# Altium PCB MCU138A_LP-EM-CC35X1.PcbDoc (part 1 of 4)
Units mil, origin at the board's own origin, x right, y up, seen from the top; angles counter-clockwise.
Board outline 2309.44 x 2672.36 mil, 4 copper layers (Top Layer, L02_GND, L03_PWR, Bottom Layer), stack 60 mil thick; 235 components, 167 nets, 678 pads, 887 vias.
Unrouted connection lines stored in the file: 19.
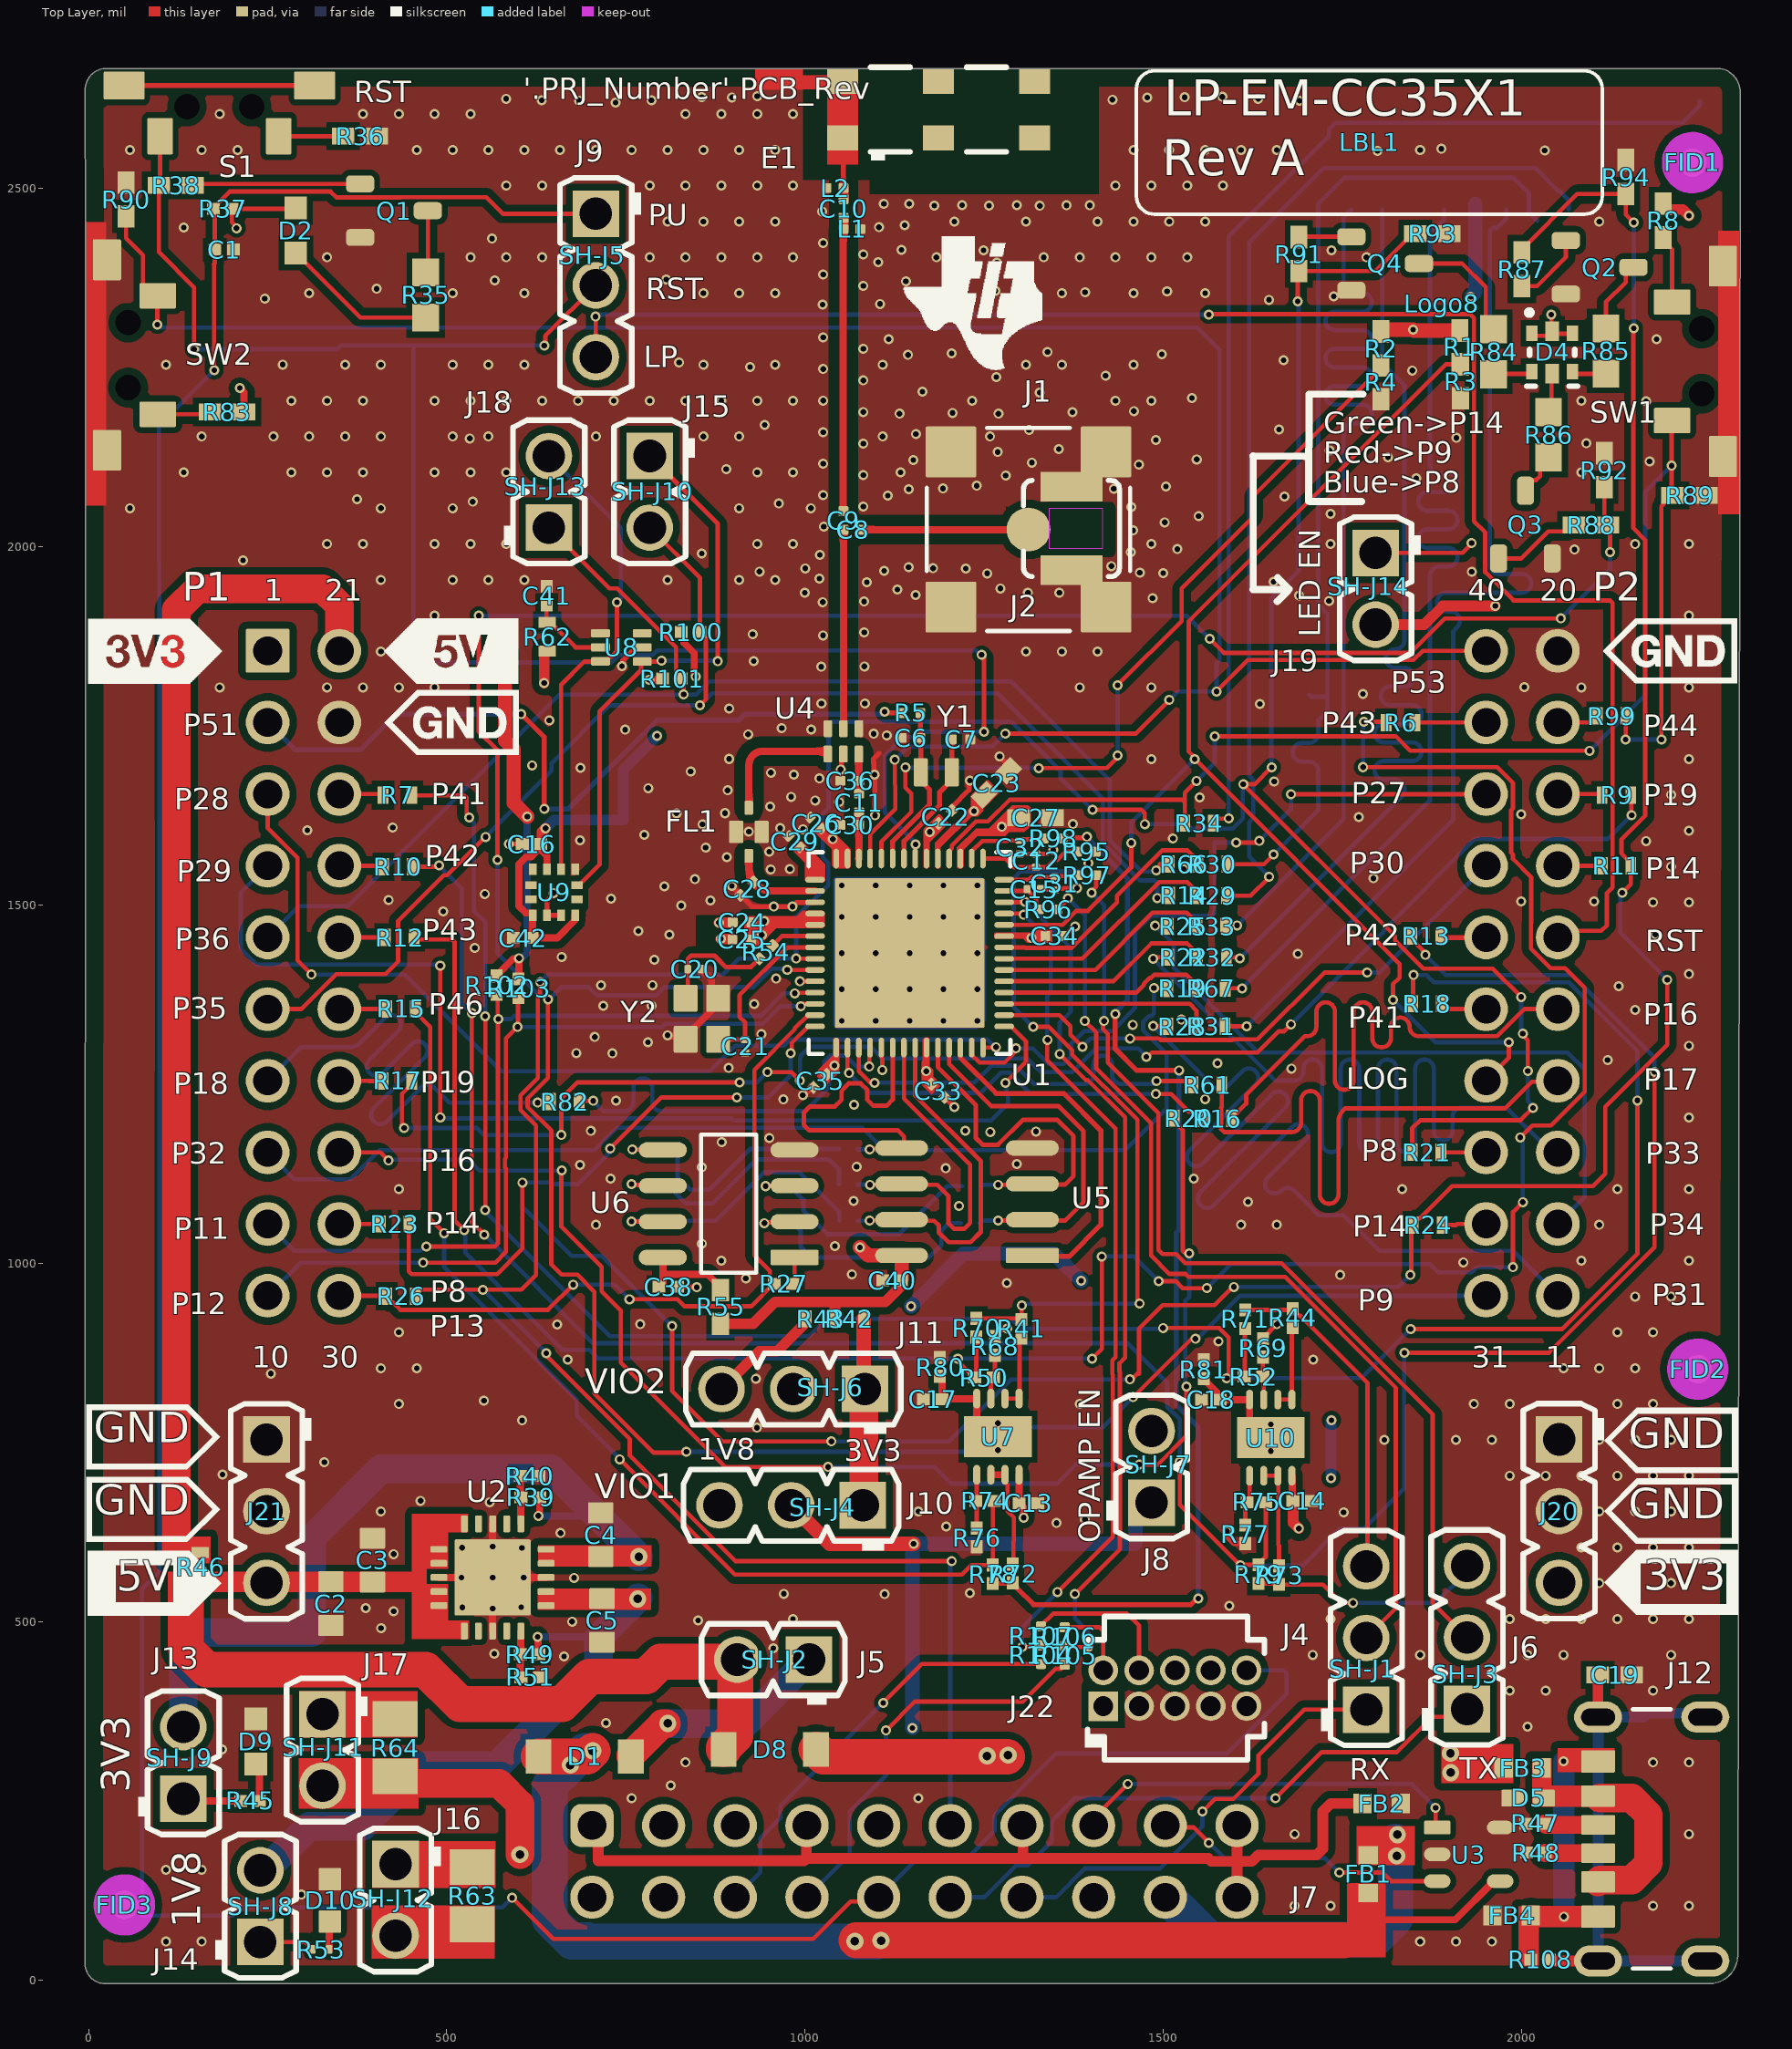
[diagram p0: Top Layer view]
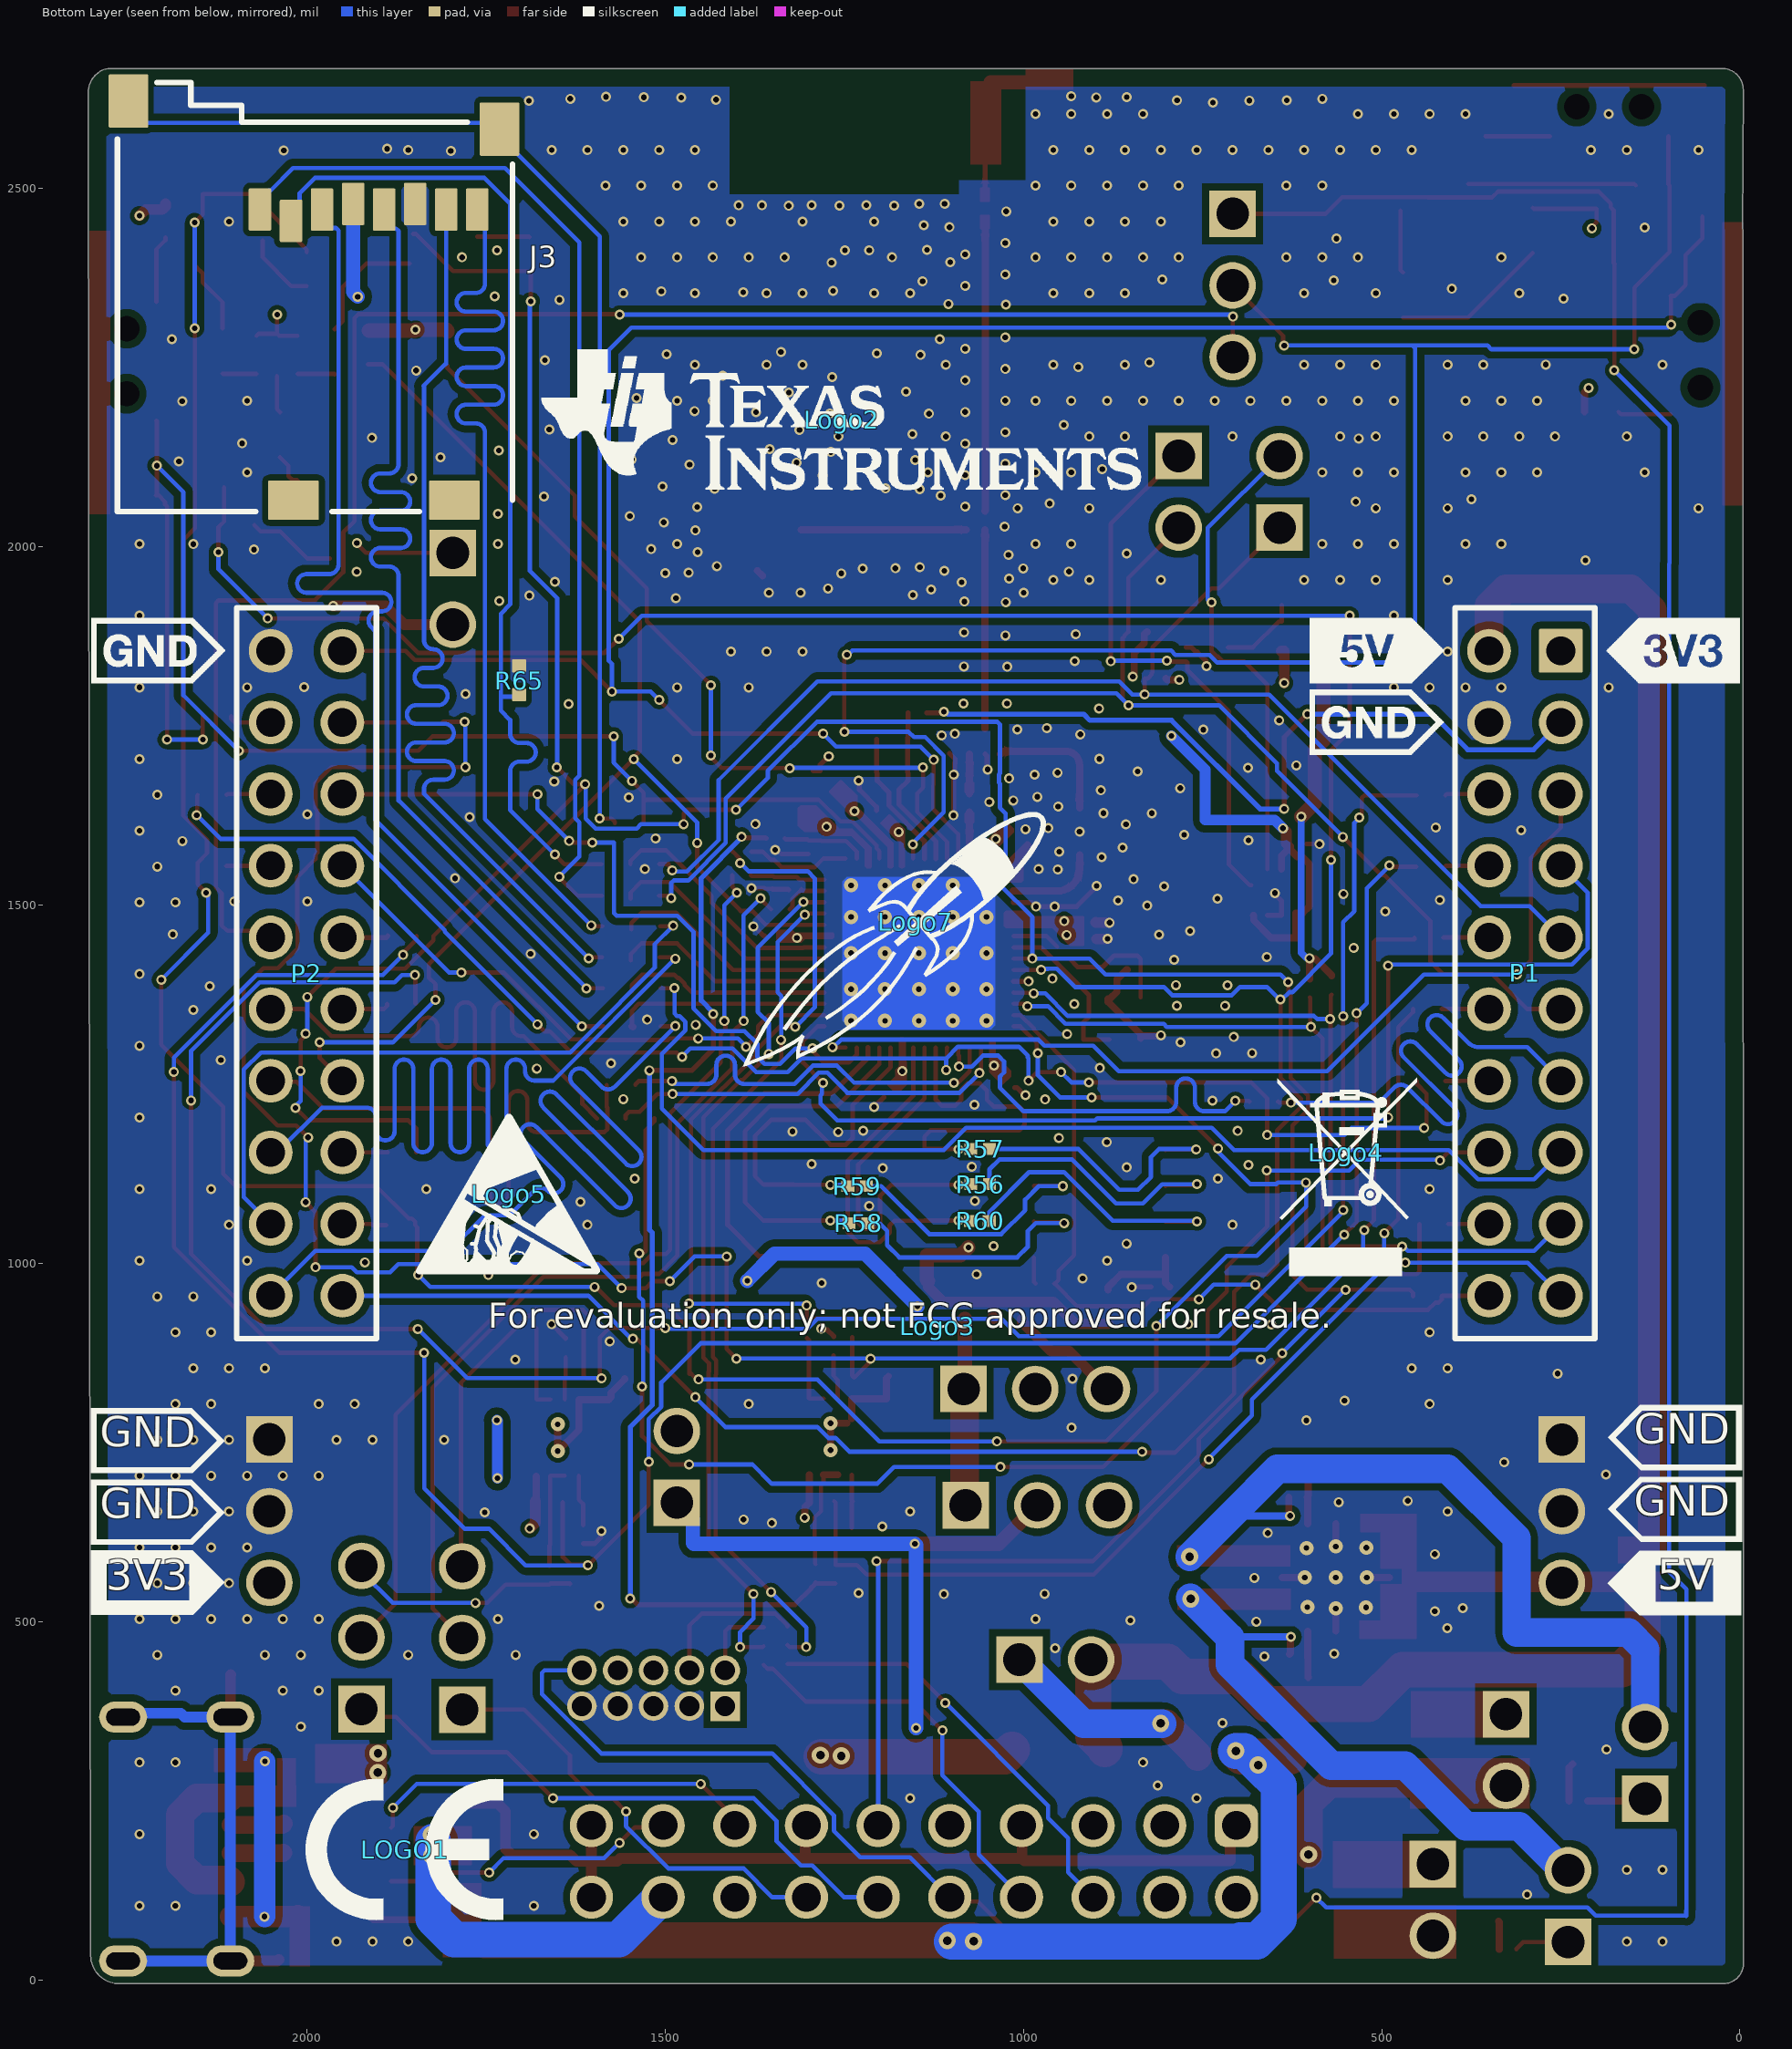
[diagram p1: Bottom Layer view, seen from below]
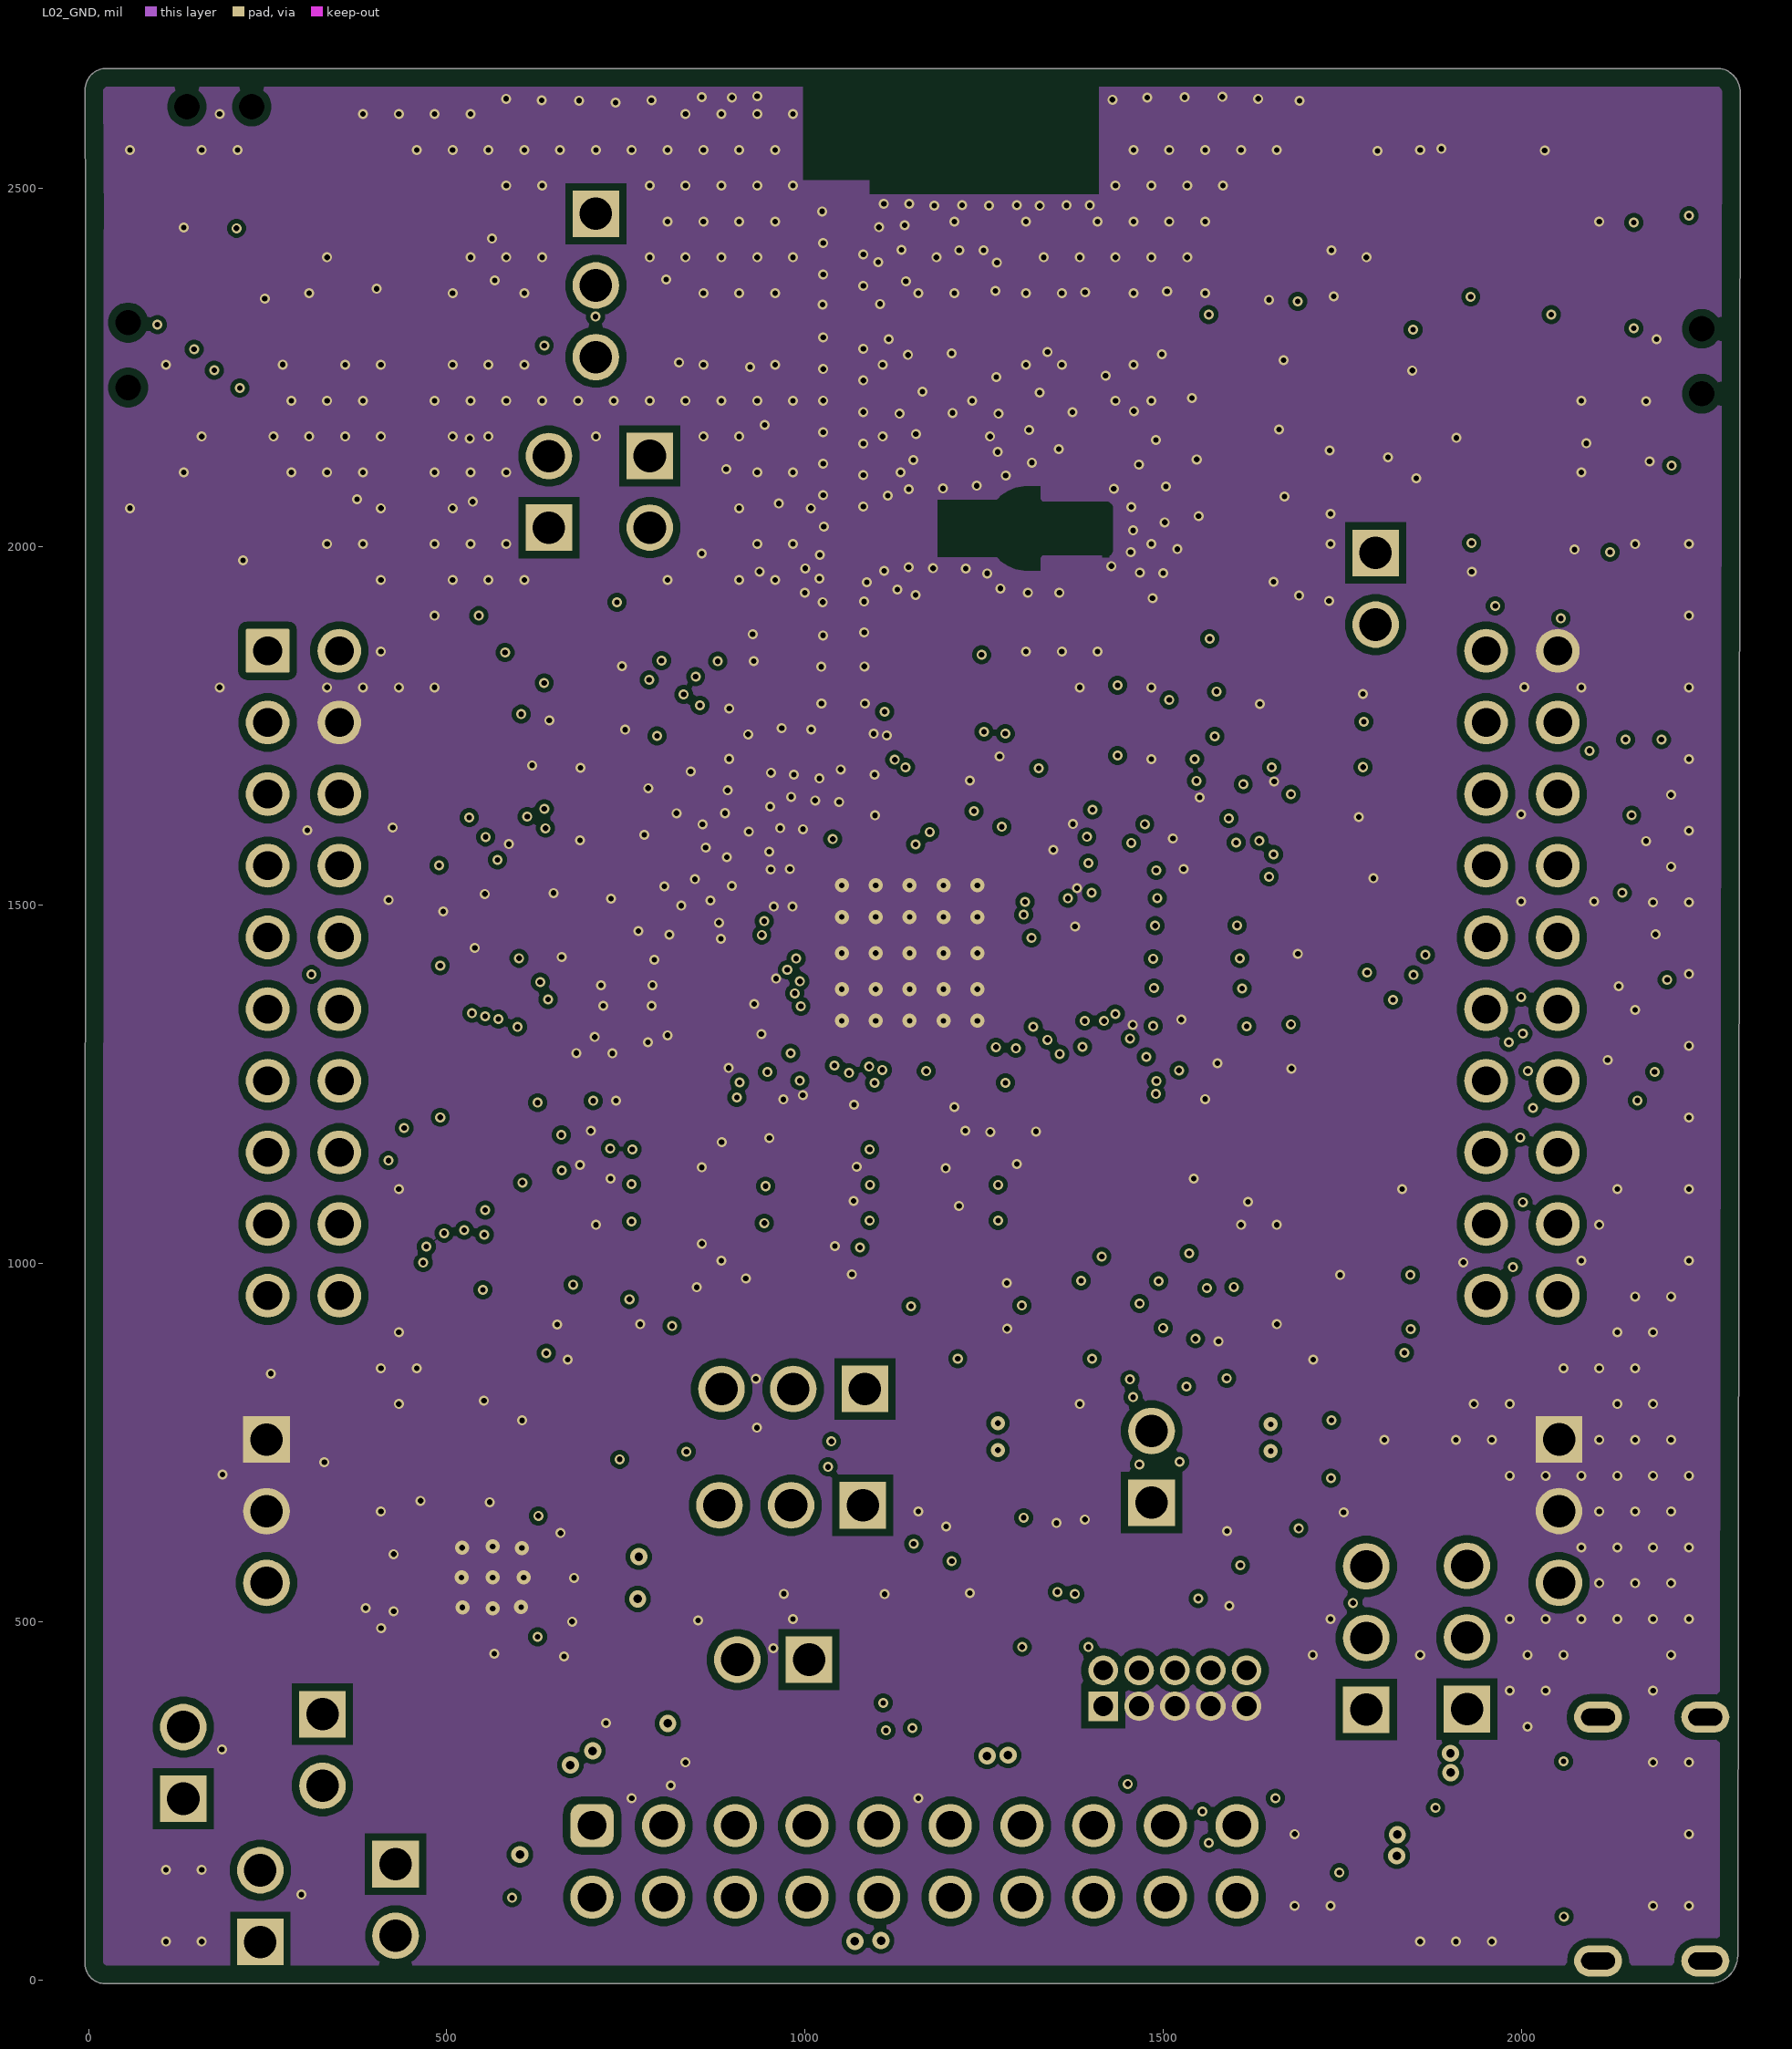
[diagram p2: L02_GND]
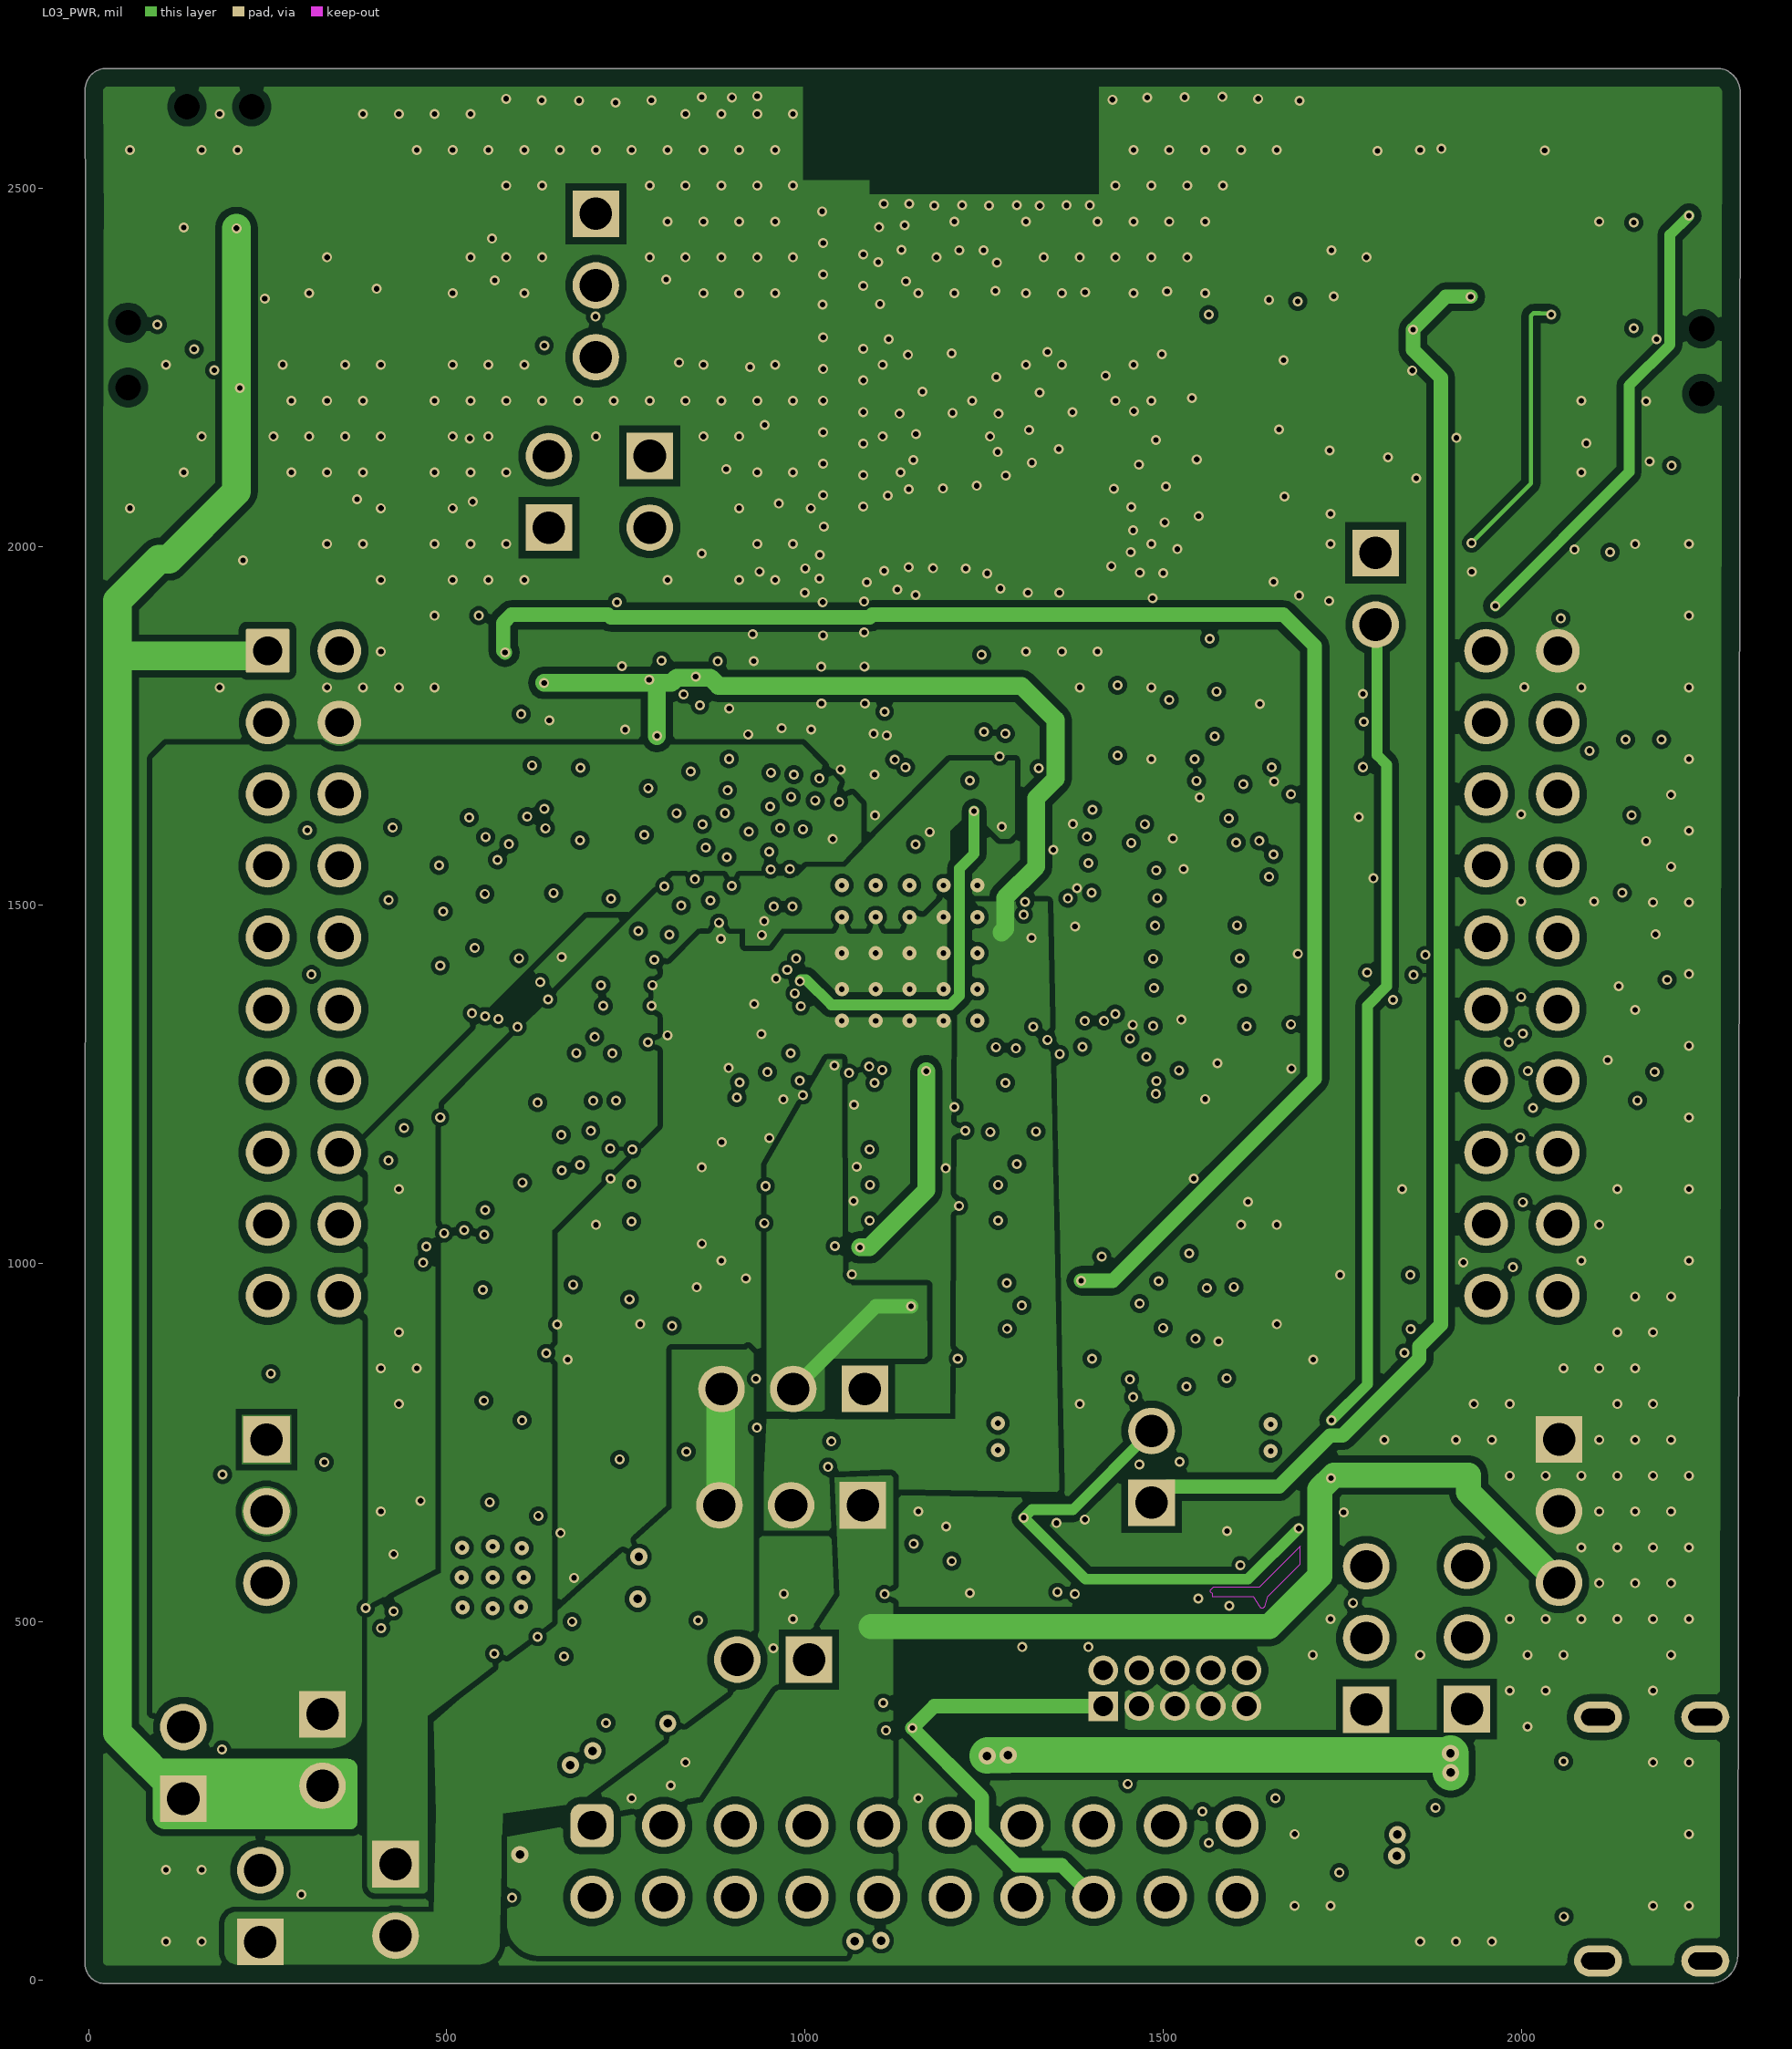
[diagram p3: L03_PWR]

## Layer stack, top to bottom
Top Solder: solder mask 1, Solder Resist, Dk 3.5
Top Layer: signal copper 1.85
Dielectric 1: prepreg 5.482, FR-4 High Tg, Dk 4.2
L02_GND: signal copper 1.26
Dielectric1: prepreg 42.816, FR-4 High Tg, Dk 4.2
L03_PWR: signal copper 1.26
Dielectric 2: prepreg 5.482, FR-4 High Tg, Dk 4.2
Bottom Layer: signal copper 1.85
Bottom Solder: solder mask 1, Solder Resist, Dk 3.5

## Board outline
24.8,2667.32 357.84,2667.33 1318.84,2667.33 2277.32,2667.33 cw(c2270.63,2633.89) 2304.73,2633.89 2301.28,34.06 cw(c2261.12,35.14) 2260.28,-5.03 24.81,-5.03 cw(c23.41,23.09) -4.71,21.75 -4.7,179.02 -4.45,2437.53 cw(c32.53,2437.53) -3.83,2444.26 -4.58,2637.83 cw(c24.8,2637.94)

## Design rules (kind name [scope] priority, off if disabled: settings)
AcuteAngle [All] p1: minimum=4.50000000000000E+0001 checktracksonly=FALSE
AssemblyTestPointUsage [All] p1: valid=2
BoardOutlineClearance BoardOutlineClearance_poly [OnCopper and IsPoly] p1: gap=25 ignorepadtopadclearanceinfootprint=FALSE
BoardOutlineClearance BoardOutlineClearance_vias [IsVia] p2: gap=30 ignorepadtopadclearanceinfootprint=FALSE
Clearance Clearance_RF [InNetClass('RF') vs InNet('GND')] p1: gap=7.87 ignorepadtopadclearanceinfootprint=TRUE except(6: Via-Poly; 7: Track-Track Track-SMDPad Track-Region; 11.25: SMDPad-Poly; 15.5: Arc-Poly Track-Poly)
Clearance Clearance_J1J2 [IsPad and InComponent('J1') vs IsKeepOut and InComponent('J2')] p2: gap=0 ignorepadtopadclearanceinfootprint=TRUE
Clearance 50ohm [InNetClass('Antenna') vs InNet('GND')] p3: gap=7.78 ignorepadtopadclearanceinfootprint=TRUE except(6: Via-Poly; 11.25: SMDPad-Poly; 15: Arc-Poly Track-Poly)
Clearance Clearance_Keepouts [((IsTrack Or IsArc) And Not InPoly) And IsFree and IsKeepOut vs ((IsTrack Or IsArc) And Not InPoly) And IsFree and IsKeepOut] p4: gap=0 ignorepadtopadclearanceinfootprint=FALSE
Clearance Clearance_Poly [InPolygon] p5: gap=10 ignorepadtopadclearanceinfootprint=TRUE except(6: Via-Poly; 8: SMDPad-Poly Poly-Poly Poly-Hole)
Clearance Clearance_FiducialMark [IsKeepOut and InComponentClass('FiducialMark') vs IsPad and InComponentClass('FiducialMark')] p6: gap=0 ignorepadtopadclearanceinfootprint=FALSE
Clearance [All] p7: gap=4 ignorepadtopadclearanceinfootprint=TRUE except(0: Via-Text)
ComponentClearance ComponentClearance_R1_C6 [InComponent('R1') vs InComponent('C6')] p1: gap=0 collisioncheckmode=3 verticalgap=0 showdistances=FALSE
ComponentClearance ComponentClearance_J1_J2 [InComponent('J1') vs InComponent('J2')] p2: gap=0 collisioncheckmode=3 verticalgap=0 showdistances=FALSE
ComponentClearance ComponentClearance_C11_C13 [InComponent('C11') vs InComponent('C13')] p3: gap=0 collisioncheckmode=3 verticalgap=0 showdistances=FALSE
ComponentClearance ComponentClearance_MountingHoles_FiducialMarks [InComponentClass('Mounting Holes') vs InComponentClass('FiducialMark')] p4: gap=50 collisioncheckmode=3 verticalgap=10 showdistances=FALSE
ComponentClearance ComponentClearance_Shunt [InComponentClass('Header') vs InComponentClass('Shunt')] p5: gap=0 collisioncheckmode=3 verticalgap=0 showdistances=FALSE
ComponentClearance ComponentClearance_Logo [InComponentClass('Logo')] p6: gap=30 collisioncheckmode=3 verticalgap=10 showdistances=FALSE
ComponentClearance ComponentClearance_ScrewToNut [(HasFootprint('NY PMS 440 0025 PH')) vs (HasFootprint('Keystone_1902C'))] p7: gap=5 collisioncheckmode=3 verticalgap=10 showdistances=FALSE
ComponentClearance ComponentClearance_MountingHoles [InComponentClass('Mounting Holes')] p8: gap=100 collisioncheckmode=3 verticalgap=100000 showdistances=FALSE
ComponentClearance ComponentClearance_SmallPassives [HasFootprint('0201*') or HasFootprint('0402*') or HasFootprint('0508') or HasFootprint('0603*') or HasFootprint('0612') or HasFootprint('0805*') or HasFootprint('0815*') or HasFootprint('0830*') or HasFootprint('1206*') or HasFootprint('1210*') or HasFootprint('1808*') or HasFootprint('1812*') or HasFootprint('1825*') or HasFootprint('2010*') or HasFootprint('2220*') or HasFootprint('2225*') or HasFootprint('2512*') or HasFootprint('2728*') or HasFootprint('3518*') vs HasFootprint('0201*') or HasFootprint('0402*') or HasFootprint('0508') or HasFootprint('0603*') or HasFootprint('0612') or HasFootprint('0805*') or HasFootprint('0815*') or HasFootprint('0830*') or HasFootprint('1206*') or HasFootprint('1210*') or HasFootprint('1808*') or HasFootprint('1812*') or HasFootprint('1825*') or HasFootprint('2010*') or HasFootprint('2220*') or HasFootprint('2225*') or HasFootprint('2512*') or HasFootprint('2728*') or HasFootprint('3518*')] p9: gap=10 collisioncheckmode=3 verticalgap=10 showdistances=FALSE
ComponentClearance ComponentClearance_THtoSMT [IsThruComponent vs IsSMTComponent] p10: gap=20 collisioncheckmode=3 verticalgap=30 showdistances=FALSE
ComponentClearance ComponentClearance_THtoTH [IsThruComponent vs IsThruComponent] p11: gap=20 collisioncheckmode=3 verticalgap=30 showdistances=FALSE
ComponentClearance [All] p12: gap=10 collisioncheckmode=3 verticalgap=10 showdistances=FALSE
DiffPairsRouting [All] p1: maxlimit=100 minlimit=10 mostfreqgap=10 toplayer_minwidth=15 toplayer_maxwidth=15 toplayer_prefwidth=15 midlayer1_minwidth=15 midlayer1_maxwidth=15 midlayer1_prefwidth=15 midlayer2_minwidth=15 midlayer2_maxwidth=15 midlayer2_prefwidth=15 bottomlayer_minwidth=15 bottomlayer_maxwidth=15 bottomlayer_prefwidth=15 maxuncoupledlength=1000
FabricationTestPointUsage TestPointUsage [All] p1: valid=2 allowmultiple=FALSE
FabricationTestpoint Testpoint [All] p1: side=3 testpointundercomponent=TRUE minsize=40 maxsize=100 preferedsize=60 minholesize=0 maxholesize=40 preferedholesize=32 testpointgrid=1 allowsidetop=TRUE allowsidebottom=TRUE usegrid=TRUE gridtolerance=0.01
FanoutControl Fanout_LCC [IsLCC] p1: bgadir=Out bgaviamode=Centered fanoutstyle=Auto fanoutdirection=Alternating viagrid=1 // Fanout_LCC (Default Rule)
FanoutControl Fanout_BGA [IsBGA] p2: bgadir=Out bgaviamode=Centered fanoutstyle=Auto fanoutdirection=Alternating viagrid=1 // Fanout_BGA (Default Rule)
FanoutControl Fanout_Default [All] p4: bgadir=Out bgaviamode=Centered fanoutstyle=Auto fanoutdirection=Alternating viagrid=1 // Fanout_Default (Default Rule)
FanoutControl Fanout_Small [(CompPinCount < 5)] p5: bgadir=Out bgaviamode=Centered fanoutstyle=Auto fanoutdirection=OutThenIn viagrid=1 // Fanout_Small (Default Rule)
HoleSize [All] p1: absolutevalues=TRUE maxlimit=251 minlimit=7.87 maxpercent=80.000 minpercent=20.000
MatchedLengths SWD_pre_lengths [InNetClass('SWD')] p1: tolerance=50 checknetsindiffpair=FALSE checkdiffpairvsdiffpair=TRUE checkxsignals=TRUE checkothers=TRUE
MatchedLengths xSPI_lengths [InNetClass('xSPI')] p2: tolerance=25 checknetsindiffpair=FALSE checkdiffpairvsdiffpair=TRUE checkxsignals=TRUE checkothers=TRUE
MatchedLengths SPI0_pre_lengths [InNetClass('SPI0_pre')] p3: tolerance=50 checknetsindiffpair=FALSE checkdiffpairvsdiffpair=TRUE checkxsignals=TRUE checkothers=TRUE
MatchedLengths SPI1_pre_lengths [InNetClass('SPI1_pre')] p4: tolerance=50 checknetsindiffpair=FALSE checkdiffpairvsdiffpair=TRUE checkxsignals=TRUE checkothers=TRUE
MatchedLengths SDMMC_pre_lengths [InNetClass('SDMMC_pre')] p5: tolerance=50 checknetsindiffpair=FALSE checkdiffpairvsdiffpair=TRUE checkxsignals=TRUE checkothers=TRUE
MatchedLengths SWD_lengths [InNetClass('SWD')] p6: tolerance=50 checknetsindiffpair=FALSE checkdiffpairvsdiffpair=TRUE checkxsignals=TRUE checkothers=TRUE
MatchedLengths SPI0_lengths [InNetClass('SPI0')] p7: tolerance=50 checknetsindiffpair=FALSE checkdiffpairvsdiffpair=TRUE checkxsignals=TRUE checkothers=TRUE
MatchedLengths SPI1_lengths [InNetClass('SPI1')] p8: tolerance=50 checknetsindiffpair=FALSE checkdiffpairvsdiffpair=TRUE checkxsignals=TRUE checkothers=TRUE
MatchedLengths SDMMC_lengths [InNetClass('SDMMC')] p9: tolerance=50 checknetsindiffpair=FALSE checkdiffpairvsdiffpair=TRUE checkxsignals=TRUE checkothers=TRUE
MinimumAnnularRing MinimumAnnularRing_ThermalPadVias [IsVia and InAnyComponent] p1: minimumring=5.91
MinimumAnnularRing [All] p2: minimumring=3
MinimumSolderMaskSliver MinimumSolderMaskSliver_Logo [InComponentClass('Logo') vs InComponentClass('Logo')] p1: minsoldermaskwidth=0.7
MinimumSolderMaskSliver [All] p2: minsoldermaskwidth=3.94
PlaneConnect [All] p1: planeconnectstyle=Relief reliefexpansion=10 reliefentries=4 reliefconductorwidth=10 reliefairgap=10
PolygonConnect [All] p1: connectstyle=Direct reliefconductorwidth=10 reliefentries=4 polygonreliefangle="90 Angle" airgapwidth=10
RoutingVias ThermalPadVias [IsVia and InAnyComponent] p1: holewidth=7.87 width=19.68 viastyle="Through Hole" minholewidth=7.87 minwidth=19.68 maxholewidth=12.99 maxwidth=23.62
RoutingVias [All] p2: holewidth=16 width=34 viastyle="Through Hole" minholewidth=7.87 minwidth=14 maxholewidth=40 maxwidth=65
SilkToBoardRegionClearance [Not ((IsComment or IsDesignator) And (Hide <> 'False')) and not InRegion(1000,500,4000,800)] p1:
SilkToSilkClearance SilkToSilkClearance_Pb-FreeLogo [(HasFootprint('Pb-Free_Overlay_Medium') OR HasFootprint('Pb-Free_Overlay_Small')) vs (HasFootprint('Pb-Free_Overlay_Medium') OR HasFootprint('Pb-Free_Overlay_Small'))] p1: silktosilkclearance=0
SilkToSilkClearance [All] p2: silktosilkclearance=3
SilkToSolderMaskClearance SilkToSolderMaskClearance_vias [IsVia] p1: minsilkscreentomaskgap=0 clearancetoexposedcopper=TRUE
SilkToSolderMaskClearance SilkToComponentPadClearance [(IsPad or IsFill or IsRegion) and InAnycomponent] p2: minsilkscreentomaskgap=0 clearancetoexposedcopper=TRUE
SilkToSolderMaskClearance "Silk to Solder Mask Opening" [All] p3: minsilkscreentomaskgap=2.49 clearancetoexposedcopper=FALSE
SolderMaskExpansion [All] p1: expansion=1.5 istentingtop=FALSE
UnRoutedNet [All] p1: checkbadconnections=TRUE
Width [All] p1: maxlimit=100 minlimit=4.6 preferedwidth=10 checkconnectedcopper=TRUE
14 further rules are at their usual default settings.

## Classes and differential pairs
net class SWD: NetJ7_6 NetJ7_8
component class Shunt: SH-J1 SH-J2 SH-J3 SH-J4 SH-J5 SH-J6 SH-J7 SH-J8 SH-J9 SH-J10 SH-J11 SH-J12 SH-J13 SH-J14
net class xSPI: xSPI_CLK xSPI_D0 xSPI_D1 xSPI_D2 xSPI_D3
net class RF: Diplexer_A_IN Diplexer_BG_IN Diplexer_out NetC8_2 NetC9_1 RF_A RF_BG
net class SPI1_pre: P31_GPIO15 P32_GPIO14 P33_GPIO13
net class SPI0_pre: P16_GPIO29 P17_GPIO28 P18_GPIO27
net class SDMMC_pre: P31_GPIO15 P32_GPIO14 P33_GPIO13 P34_GPIO12 P35_GPIO11 P36_GPIO10
net class SWD_pre: SWCLK SWDIO
net class SPI0: SPI0_CLK SPI0_PICO SPI0_POCI
net class SPI1: SPI1_CLK SPI1_PICO SPI1_POCI
net class SDMMC: SDMMC_CLK SDMMC_CMD SDMMC_D0 SDMMC_D1 SDMMC_D2 SDMMC_D3
component class MCU138A_Power: C2 C3 C4 C5 C16 C19 C41 C42 D4 D5 D8 D9 D10 FB3 FB4 J10 J11 J12 J13 J14 J15 J16 J17 J18 J19 J20 J21 Q2 Q3 Q4 R8 R39 R40 R42 R43 R45 R46 R47 R48 R49 R51 R53 R62 R63 R64 R83 R84 R85 R86 R87 R88 R89 R90 R91 R92 R93 R94 R108 SW1 SW2 U2 U8 U9
component class MCU138A_HostInterface: C1 C12 C13 C14 C15 C17 C18 C31 C32 D1 D2 FB1 FB2 J3 J4 J5 J6 J7 J8 J9 J22 P1 P2 Q1 R6 R7 R9 R10 R11 R12 R13 R14 R15 R16 R17 R18 R19 R20 R21 R22 R23 R24 R25 R26 R28 R29 R30 R31 R32 R33 R34 R35 R36 R37 R38 R41 R44 R50 R52 R61 R65 R66 R67 R68 R69 R70 R71 R72 R73 R74 R75 R76 R77 R78 R79 R80 R81 R82 R95 R96 R97 R98 R99 R100 R101 R102 R103 R104 R105 R106 R107 S1 U3 U7 U10
component class MCU138A_EngineArea: C6 C7 C8 C9 C10 C11 C20 C21 C22 C23 C24 C25 C26 C27 C28 C29 C30 C33 C34 C35 C36 C38 C40 E1 FL1 J1 J2 L1 L2 R1 R2 R3 R4 R5 R27 R54 R55 R56 R57 R58 R59 R60 U1 U4 U5 U6 Y1 Y2
component class Header: J4 J5 J6 J8 J9 J10 J11 J13 J14 J15 J16 J17 J18 J19 J20 J21
component class Logo: Logo2 Logo8
component class MCU138A_Hardware: FID1 FID2 FID3 LBL1 LOGO1 Logo2 Logo3 Logo4 Logo5 Logo7 Logo8 SH-J1 SH-J2 SH-J3 SH-J4 SH-J5 SH-J6 SH-J7 SH-J8 SH-J9 SH-J10 SH-J11 SH-J12 SH-J13 SH-J14 ZZ1 ZZ2 ZZ3 ZZ4
component class FiducialMark: FID1 FID2 FID3
component class AssemblyNote: ZZ1 ZZ2 ZZ3 ZZ4
component class Label: LBL1

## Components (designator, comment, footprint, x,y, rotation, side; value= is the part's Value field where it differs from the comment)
C1 "GRM033C71A104KE14D" 0201#1 189.24,2414.87 r0 top value=0.1uF
C2 "GRM188Z71A106MA73J" FP-GRM188Z71A106MA73J_0603-MFG 338.12,525.31 r90 top value=10µF
C3 "GRM188Z71A106MA73J" FP-GRM188Z71A106MA73J_0603-MFG 396.25,586.02 r270 top value=10µF
C4 "GRM188Z71A106MA73J" FP-GRM188Z71A106MA73J_0603-MFG 714.8,621.44 r270 top value=10µF
C5 "GRM188Z71A106MA73J" FP-GRM188Z71A106MA73J_0603-MFG 716.5,501.99 r90 top value=10µF
C6 "GRM0335C1H4R7BA01D" 0201_033 1147.41,1733.28 r180 top value=4.7pF
C7 "GRM0335C1H4R7BA01D" 0201_033 1217.33,1731.05 r0 top value=4.7pF
C8 "GRM0335C1H2R4BA01D" FP-GRM0335C1H2R4BA01D_0201-MFG 1066.4,2023.77 r0 top value=2.4pF
C9 "GRM0335C1H2R4BA01D" FP-GRM0335C1H2R4BA01D_0201-MFG 1053.38,2036.84 r270 top value=2.4pF
C10 "GRM0335C1H2R4BA01D" FP-GRM0335C1H2R4BA01D_0201-MFG 1053.41,2471.96 r90 top value=2.4pF
C11 "GRM0335C1H2R4BA01D" FP-GRM0335C1H2R4BA01D_0201-MFG 1075.15,1642.59 r270 top value=2.4pF
C12 "GRM0335C1E331FA01D" FP-GRM0335C1E331FA01D_0201-MFG 1322.02,1562.11 r90 top value=330pF
C13 "GRM033C71A104KE14D" 0201#1 1311.33,665.56 r180 top value=0.1uF
C14 "GRM033C71A104KE14D" 0201#1 1693.48,668.7 r180 top value=0.1uF
C15 "GRM0335C1E331FA01D" FP-GRM0335C1E331FA01D_0201-MFG 1319.06,1522.27 r0 top value=330pF
C16 "GRM033C71A104KE14D" 0201#1 618.25,1585.22 r180 top value=0.1uF
C17 "GRM033C71A104KE14D" 0201#1 1178.02,810.73 r0 top value=0.1uF
C18 "GRM033C71A104KE14D" 0201#1 1566.02,810.02 r180 top value=0.1uF
C19 "C0402C103K4RACTU" 0402 2129.51,426.07 r0 top value=0.01uF
C20 "GRM0335C1H6R2BA01D" FP-GRM0335C1H6R2BA01D_0201-MFG 845.69,1410.59 r180 top value=6.2pF
C21 "GRM0335C1H6R2BA01D" FP-GRM0335C1H6R2BA01D_0201-MFG 916.2,1302.99 r270 top value=6.2pF
C22 "GRM033C71A104KE14D" 0201#2 1195.55,1623.1 r45 top value=0.1uF
C23 "GRM155R70J105MA12D" 0402 1266.82,1670.56 r225 top value=1uF
C24 "GRM033C71A104KE14D" 0201#2 911.94,1475.94 r180 top value=0.1uF
C25 "GRM033C71A104KE14D" 0201#2 911.65,1451.98 r180 top value=0.1uF
C26 "GRM033D70J105ME01D" FP-GRM033D70J105ME01D_0201-MFG 1014.71,1614.47 r315 top value=1µF
C27 "GRM155R70J105MA12D" 0402 1321.38,1621.88 r0 top value=1uF
C28 "GRM0335C1H1R0CA01D" FP-GRM0335C1H1R0CA01D_0201-MFG 918.88,1522.92 r45 top value=1pF
C29 "GRM033D70J105ME01D" FP-GRM033D70J105ME01D_0201-MFG 984.98,1588.55 r315 top value=1µF
C30 "GRM0335C1H2R4BA01D" FP-GRM0335C1H2R4BA01D_0201-MFG 1062.15,1611.99 r0 top value=2.4pF
C31 "GRM0335C1E331FA01D" FP-GRM0335C1E331FA01D_0201-MFG 1347.92,1530.03 r270 top value=330pF
C32 "GRM0335C1E331FA01D" FP-GRM0335C1E331FA01D_0201-MFG 1299.55,1580.69 r270 top value=330pF
C33 "GRM033C71A104KE14D" 0201#2 1185.39,1240.82 r315 top value=0.1uF
C34 "GRM033C71A104KE14D" 0201#2 1348.09,1456.88 r0 top value=0.1uF
C35 "GRM033C71A104KE14D" 0201#2 1020.81,1254.67 r225 top
C36 "GRM0335C1H2R4BA01D" FP-GRM0335C1H2R4BA01D_0201-MFG 1062.13,1673.33 r0 top value=2.4pF
C38 "GRM033C71A104KE14D" 0201#1 808.74,967.29 r0 top value=0.1uF
C40 "GRM033C71A104KE14D" 0201#1 1121.22,976.28 r180 top value=0.1uF
C41 "GRM033C71A104KE14D" 0201#1 639.21,1931.74 r90 top value=0.1uF
C42 "GRM033C71A104KE14D" 0201#1 605.83,1454.12 r180 top value=0.1uF
D1 "MBR130T1G" SOD-123 692.36,311.85 r180 top value=30V
D2 "CMP-0002892-2" WL-SMCW_YELLOW 289.27,2441.35 r90 top value=Yellow
D4 "CMP-0003017-2" EAST1616_RGB 2042.19,2271.22 r0 top value=Rgb
D5 "ESD5B5.0ST1G" SOD-523F_Bi 2008.68,253.81 r180 top value=5V
D8 "MBR130T1G" SOD-123 950.77,321.96 r0 top value=30V
D9 "CMP-0002905-1" WL-SMCW_GREEN 233.41,333.12 r270 top value=Green
D10 "CTL0603FRD1T" FP-CTL0603FRD1T_0603-MFG 336.86,111.35 r270 top
E1 "M830520" Ethertronics_M830520 1185.98,2609.94 r90 top
FB1 "BLM18PG471SN1D" FP-BLM18-0_15-t0_8-MFG 1785.48,147.8 r270 top
FB2 "BLM18PG471SN1D" FP-BLM18-0_15-t0_8-MFG 1804.15,246.48 r0 top
FB3 "BLM18PG471SN1D" FP-BLM18-0_15-t0_8-MFG 2001,295.91 r180 top
FB4 "BLM18PG471SN1D" FP-BLM18-0_15-t0_8-MFG 1985.64,90.21 r180 top
FID1 "Fiducial" Fiducial10-20 2237.99,2535.97 r0 top
FID2 "Fiducial" Fiducial10-20 2245.37,852.49 r0 top
FID3 "Fiducial" Fiducial10-20 50.01,104.95 r0 top
FL1 "DEA162450BT-1295A1" FP-DEA162450BT-1295A1_SMT_FILTER_1MM60_0MM80-MFG 921.39,1602.25 r90 top
J1 "PCB.SMAFSTJ.B.HT" FP-PCB.SMAFSTJ.B.HT_SMT_SMA_JACK-MFG 1311.55,2024.13 r0 top
J2 "U.FL-R-SMT-1(01)" CONN_UFL-R-SMT-1 1371.62,2025.54 r0 top
J3 "693071010811" Molex_693071010811 1988.51,2348.43 r180 bottom locked
J4 "CMP-0054796-1" WURTH_61300311121 1782.8,477.38 r90 top
J5 "61300211121" WURTH_61300211121 955.26,447.16 r180 top
J6 "CMP-0054796-1" WURTH_61300311121 1923.3,478.12 r90 top
J7 "SFH11-PBPC-D10-RA-BK" Sullins_SFH11-xxxC-D10-RA 1152.5,165.64 r0 top
J8 "61300211121" WURTH_61300211121 1483.3,716.19 r90 top
J9 "CMP-0054796-1" WURTH_61300311121 707.96,2364.64 r270 top
J10 "CMP-0054796-1" WURTH_61300311121 980.36,662.51 r180 top
J11 "CMP-0054796-1" WURTH_61300311121 983.3,824.84 r180 top
J12 "USB4125-GF-A-0190" FP-USB4125-GF-A-0190_CONN_USB-MFG 2224.42,196.85 r90 top
J13 "61300211121" WURTH_61300211121 132.3,303.09 r90 top
J14 "61300211121" WURTH_61300211121 239.78,103.23 r90 top
J15 "61300211121" WURTH_61300211121 783.15,2076.76 r270 top
J16 "61300211121" WURTH_61300211121 428.48,111.8 r270 top
J17 "61300211121" WURTH_61300211121 326.5,321.11 r270 top
J18 "61300211121" WURTH_61300211121 642.46,2076.58 r90 top
J19 "CMP-0054794-1" WURTH_61300211121 1795.91,1941.39 r270 top
J20 "CMP-0054796-1" WURTH_61300311121 2051.8,654.48 r270 top
J21 "CMP-0054796-1" WURTH_61300311121 248.43,654.21 r270 top
J22 "CMP-0075533-1" Samtec_FTSH-105-01-x-D-K 1515.87,407.24 r90 top
L1 "LQP03HQ3N9B02D" FP-LQP03HQ3N9B02D_0201-MFG 1065.17,2443.28 r180 top value=3.9nH
L2 "LQP03HQ3N9B02D" FP-LQP03HQ3N9B02D_0201-MFG 1041.55,2500.57 r0 top value=3.9nH
LBL1 "THT-14-423-10" Label_650x200 1787.19,2564 r0 top
LOGO1 "CE Mark" CE_Mark_5mm 1863.27,182.15 r180 bottom
Logo2 "Texas Instruments" TI_Stacked_Overlay_Small 1253.79,2177.31 r180 bottom
Logo3 "FCC disclaimer" FCC_disclaimer 1119.78,912.48 r180 bottom
Logo4 "WEEE logo" WEEE_Minimum 550.21,1154.59 r180 bottom
Logo5 "ESD Susceptible" ESD_Overlay_Medium 1717.96,1096.27 r180 bottom
Logo7 "LaunchPad Rocket" LaunchPadRocket_Small 1150.33,1476.42 r180 bottom
Logo8 "Texas Instruments" TI_Horizontal_Overlay_Medium 1887.95,2339.84 r0 top
P1 "SSQ-110-03-T-D" BoosterPack_40pin_J1J3 299.99,1404.89 r180 bottom locked
P2 "SSQ-110-03-T-D" BoosterPack_40pin_J2J4 1999.99,1404.89 r180 bottom locked
Q1 "CMP-0000755-1" SOT-23 426.26,2468.99 r0 top value=50V
Q2 "CMP-0000755-1" SOT-23 2108.45,2390.03 r0 top value=50V
Q3 "CMP-0000755-1" SOT-23 2004.94,2030.96 r90 top value=50V
Q4 "CMP-0000755-1" SOT-23 1809.23,2395.21 r0 top value=50V
R1 "RC0402FR-0710KL" 0402 1913.09,2278.15 r270 top value=10.0k
R2 "RC0402FR-0710KL" 0402 1803.11,2276.73 r270 top value=10.0k
R3 "RC0402FR-0710KL" 0402 1914.33,2230.97 r270 top value=10.0k
R4 "RC0402FR-0710KL" 0402 1803.52,2229.41 r270 top value=10.0k
R5 "CRCW02010000Z0ED" 0201#3 1147.65,1768.12 r180 top value=0
R6 "CMP-0026992-2" 0402S 1830.52,1754.59 r180 top value=0
R7 "CMP-0026992-2" 0402S 431.02,1653.17 r180 top value=0
R8 "CMP-0026852-3" 0402 2196.85,2455.2 r270 top value=1.0k
R9 "CMP-0026992-2" 0402S 2131.98,1653.58 r180 top value=0
R10 "CMP-0026992-2" 0402S 431.54,1553.55 r180 top value=0
R11 "CMP-0026992-2" 0402S 2132.06,1554.65 r180 top value=0
R12 "CMP-0026992-2" 0402S 434.15,1454.73 r180 top value=0
R13 "CMP-0026992-2" 0402S 1866.57,1456.82 r180 top value=0
R14 "CMP-0026992-2" 0402S 1528.38,1513.24 r0 top value=0
R15 "CMP-0026992-2" 0402S 436.19,1355.07 r180 top value=0
R16 "CMP-0026992-2" 0402S 1574.73,1202.27 r0 top value=0
R17 "CMP-0026992-2" 0402S 430.89,1254.63 r180 top value=0
R18 "CMP-0026992-2" 0402S 1867.6,1362.41 r180 top value=0
R19 "CMP-0026992-2" 0402S 1526.25,1383.87 r0 top value=0
R20 "CMP-0026992-2" 0402S 1534.83,1202.58 r180 top value=0
R21 "CMP-0026992-2" 0402S 1866.84,1155.21 r180 top value=0
R22 "CMP-0026992-2" 0402S 1527.5,1427.31 r180 top value=0
R23 "CMP-0026992-2" 0402S 427.09,1054.98 r180 top value=0
R24 "CMP-0026992-2" 0402S 1868.54,1053.55 r180 top value=0
R25 "CMP-0026992-2" 0402S 1526.91,1470.42 r180 top value=0
R26 "CMP-0026992-2" 0402S 436.16,954.26 r180 top value=0
R27 "CRCW02010000Z0ED" 0201#1 969.69,971.7 r0 top value=0
R28 "CMP-0026992-2" 0402S 1525.98,1330.81 r180 top value=0
R29 "CMP-0026992-2" 0402S 1567.83,1513.12 r180 top value=0
R30 "CMP-0026992-2" 0402S 1568.18,1557.17 r180 top value=0
R31 "CMP-0026992-2" 0402S 1565.82,1330.85 r180 top value=0
R32 "CMP-0026992-2" 0402S 1567.5,1427.38 r180 top value=0
R33 "CMP-0026992-2" 0402S 1566.84,1470.41 r180 top value=0
R34 "CMP-0026992-2" 0402S 1549.66,1614.36 r180 top value=0
R35 "CMP-0025852-4" 0603 470.21,2351.31 r90 top value=750
R36 "CMP-0026656-1" 0402 378.92,2572.96 r0 top value=100
R37 "RC0201JR-7D10KL" 0201#1 187.21,2471.58 r0 top value=10k
R38 "CMP-0026825-5" 0402 121.78,2504.22 r0 top value=10k
R39 "RC0201FR-0733K2L" 0201#1 616.49,673.93 r0 top value=33.2k
R40 "RC0201FR-0710K7L" 0201#1 615.64,703.44 r180 top value=10.7k
R41 "CRCW02010000Z0ED" 0201#1 1301.51,908.63 r90 top value=0
R42 "CMP-0026992-2" 0402S 1061.5,922.76 r0 top value=0
R43 "CMP-0026992-2" 0402S 1021.5,922.76 r0 top value=0
R44 "CRCW02010000Z0ED" 0201#1 1680.17,923.76 r90 top value=0
R45 "RC0201JR-7D2KL" 0201#1 225.38,250.04 r180 top value=2.0k
R46 "CMP-0026992-2" 0402S 155.95,576.81 r90 top value=0
R47 "RC0201FR-075K1L" 0201#1 2018.63,218.44 r0 top value=5.10k
R48 "RC0201FR-075K1L" 0201#1 2019.46,177.76 r180 top value=5.10k
R49 "RC0201FR-7D13K7L" 0201#1 615.68,454.64 r0 top value=13.7k
R50 "CRCW02010000Z0ED" 0201#1 1249.42,840.95 r0 top value=0
R51 "RC0201JR-0711KL" 0201#1 616.28,422.54 r180 top value=11k
R52 "CRCW02010000Z0ED" 0201#1 1625.48,842.21 r0 top value=0
R53 "ERJ-1GNF49R9C" FP-ERJ-1GNF49R9C_0201-MFG 323.91,42.82 r180 top value=49.9
R54 "RC0201FR-7D150RL" 0201#2 945.27,1434.44 r225 top value=150
R55 "CRCW04020000Z0ED" 0402 881.8,939.32 r270 top value=0
R56 "CRCW02010000Z0ED" 0201#1 1060.16,1110.41 r180 bottom value=0
R57 "CRCW02010000Z0ED" 0201#1 1060.16,1159.51 r180 bottom value=0
R58 "CRCW02010000Z0ED" 0201#1 1230.15,1056.31 r180 bottom value=0
R59 "CRCW02010000Z0ED" 0201#1 1231.76,1107.86 r180 bottom value=0
R60 "CRCW02010000Z0ED" 0201#1 1060.43,1059.43 r180 bottom value=0
R61 "CMP-0026992-2" 0402S 1561.19,1249.07 r0 top value=0
R62 "CMP-0026992-2" 0402S 640.12,1874.56 r270 top value=0
R63 "CMP-0021515-2" 0805_HV 535.46,117.77 r90 top value=0.1
R64 "CMP-0021515-2" 0805_HV 428.1,324.37 r90 top value=0.1
R65 "ERJ-2GEJ514X" FP-ERJ-2GEJ514X_0402-MFG 1703.53,1813.69 r270 bottom value=510k
R66 "CMP-0026992-2" 0402S 1528.18,1557.28 r0 top value=0
R67 "CMP-0026992-2" 0402S 1566.18,1383.99 r180 top value=0
R68 "RC0201DR-07100KL" 0201#1 1264.71,884.82 r270 top value=100k
R69 "RC0201DR-07100KL" 0201#1 1638.56,882.15 r270 top value=100k
R70 "CRCW02010000Z0ED" 0201#1 1238.73,910.25 r90 top value=0
R71 "CRCW02010000Z0ED" 0201#1 1613.79,922.17 r90 top value=0
R72 "CRCW02010000Z0ED" 0201#1 1289.73,567.32 r270 top value=0
R73 "CRCW02010000Z0ED" 0201#1 1661.27,564.97 r270 top value=0
R74 "CRCW02010000Z0ED" 0201#1 1250.89,668.3 r180 top value=0
R75 "CRCW02010000Z0ED" 0201#1 1629.53,666.76 r180 top value=0
R76 "RC0201DR-07100KL" 0201#1 1239.37,617.66 r90 top value=100k
R77 "RC0201DR-07100KL" 0201#1 1613.95,621.97 r90 top value=100k
R78 "CRCW02010000Z0ED" 0201#1 1261.8,566.31 r270 top value=0
R79 "CRCW02010000Z0ED" 0201#1 1632.36,566.5 r270 top value=0
R80 "CRCW02010000Z0ED" 0201#1 1188.03,855.52 r270 top value=0
R81 "CRCW02010000Z0ED" 0201#1 1555.93,852.34 r270 top value=0
R82 "CMP-0026992-2" 0402S 664.5,1225.81 r0 top value=0
R83 "CMP-0026852-3" 0402 193.25,2188.22 r180 top value=1.0k
R84 "CMP-0025939-3" 0603 1960.6,2272.14 r270 top value=750
R85 "CMP-0025939-3" 0603 2117.21,2273.08 r270 top value=750
R86 "CMP-0025939-3" 0603 2037.12,2156.43 r90 top value=750
R87 "CMP-0026992-2" 0402 1999.72,2387.31 r270 top value=0
R88 "CMP-0026992-2" 0402 2096.4,2030.24 r180 top value=0
R89 "CMP-0026825-5" 0402 2233.79,2071.76 r0 top value=10k
R90 "CMP-0026825-5" 0402 52.45,2484.65 r90 top value=10k
R91 "CMP-0026992-2" 0402 1688.91,2408.43 r90 top value=0
R92 "CMP-0026823-3" 0402 2115.15,2106.77 r90 top value=100k
R93 "CMP-0026823-3" 0402 1875.07,2436.62 r0 top value=100k
R94 "CMP-0026823-3" 0402 2144.85,2515.87 r90 top value=100k
R95 "CRCW02010000Z0ED" 0201#2 1392.34,1574.55 r180 top value=0
R96 "CRCW02010000Z0ED" 0201#2 1338.88,1494.01 r0 top value=0
R97 "CRCW02010000Z0ED" 0201#2 1393.15,1541.67 r0 top value=0
R98 "CRCW02010000Z0ED" 0201#2 1345.86,1593.09 r180 top value=0
R99 "CMP-0026992-2" 0402S 2125.07,1763.93 r180 top value=0
R100 "RC0201FR-072K55L" 0201#1 840.01,1881.11 r180 top value=2.55k
R101 "RC0201FR-072K55L" 0201#1 814.08,1816.17 r180 top value=2.55k
R102 "RC0201FR-072K55L" 0201#1 569.59,1388.21 r90 top value=2.55k
R103 "RC0201FR-072K55L" 0201#1 600.2,1384.11 r90 top value=2.55k
R104 "CRCW02010000Z0ED" 0201#2 1328.89,454.01 r90 top value=0
R105 "CRCW02010000Z0ED" 0201#2 1362.24,452.99 r90 top value=0
R106 "CRCW02010000Z0ED" 0201#2 1361.99,479.21 r270 top value=0
R107 "CRCW02010000Z0ED" 0201#2 1328.89,480.48 r270 top value=0
R108 "CRCW02010000Z0ED" 0201#1 2025.19,28.69 r180 top value=0
S1 "1188E-1K2-V-TR" SW_1188E 182.59,2600.35 r270 top
SH-J1 "Place J4: 1-2" SNT-100-BK-G 1777.21,434.9 r90 top value=1x2
SH-J2 "Place J5: 1-2" SNT-100-BK-G 957.08,447.37 r180 top value=1x2
SH-J3 "Place J6: 1-2" SNT-100-BK-G 1921.13,427.1 r270 top value=1x2
SH-J4 "Place J8: 1-2" SNT-100-BK-G 1024.1,659.86 r180 top value=1x2
SH-J5 "Place J9: 1-2" SNT-100-BK-G 702.37,2407.12 r90 top value=1x2
SH-J6 "Place J10: 1-2" SNT-100-BK-G 1034.7,827.29 r180 top value=1x2
SH-J7 "Place J11: 1-2" SNT-100-BK-G 1492.42,719.47 r270 top value=1x2
SH-J8 "Place J13: 1-2" SNT-100-BK-G 239.95,103.45 r90 top value=1x2
SH-J9 "Place J14: 1-2" SNT-100-BK-G 126.71,310.61 r90 top value=1x2
SH-J10 "Place J15: 1-2" SNT-100-BK-G 786.69,2077.3 r90 top value=1x2
SH-J11 "Place J16: 1-2" SNT-100-BK-G 327.27,325.1 r90 top value=1x2
SH-J12 "Place J17: 1-2" SNT-100-BK-G 423.77,113.84 r90 top value=1x2
SH-J13 "Place J18: 1-2" SNT-100-BK-G 636.87,2084.1 r90 top value=1x2
SH-J14 "Place J19: 1-2" SNT-100-BK-G 1785.58,1945.36 r90 top value=1x2
SW1 "CMP-0002328-1" SW_1188E 2237.12,2258.82 r180 top
SW2 "CMP-0002328-1" SW_1188E 69.16,2267.48 r0 top
U1 "CC3501ENJARSHR" RSH0056D-MFG 1145.68,1433.08 r0 top
U2 "TPS7A8801RTJR" RTJ0020D 563.88,561.81 r0 top
U3 "CAT24C08TDI-GT3" FP-CAT24C08TDI-GT3_TSOT-23-5-IPC_C 1925.75,175.48 r0 top
U4 "DPX167125DT-8197B1" FP-DPX167125DT-8197B1_SMD6-MFG 1053.29,1728.48 r180 top
U5 "IS25WJ064F-JNLE" FP-IS25WJ032F-JNLE_SOIC8-IPC_C 1225.68,1086.02 r180 top
U6 "APS1604M-SQRX-SN" FP-APS1604M-SQRX-SN_SOP8-IPC_C 893.21,1083.35 r180 top
U7 "OPA2211AIDRGR" DRG0008B 1268.91,758.27 r270 top
U8 "TMP1075NDRL" DRL0006A-MFG 743.51,1859.63 r180 top
U9 "BMA456" 12LGA 649.5,1517.93 r270 top
U10 "OPA2211AIDRGR" DRG0008B 1649.53,756.85 r270 top
Y1 "TZ3359DAAO73" FP-TZ3359DAAO73_SMT2_1MM65_1MM05-MFG 1182.83,1685.39 r0 top
Y2 "TZ3716BAAO42" FP-TZ3877AAAO44_SMT4_2MM05_1MM65-MFG 855.86,1341.35 r270 top
ZZ1 "This Assembly Note is for PCB labels only" AssemblyNoteLabel 125.95,5621.08 r0 top
ZZ2 "These assemblies are ESD sensitive, ESD precautions shall be observed." AssemblyNote 125.95,5512.19 r0 top
ZZ3 "These assemblies must be clean and free from flux and all contaminants. Use of no clean flux is not acceptable." AssemblyNote 125.95,5423.63 r0 top
ZZ4 "These assemblies must comply with workmanship standards IPC-A-610 Class 2, unless otherwise specified." AssemblyNote 125.95,5335.08 r0 top

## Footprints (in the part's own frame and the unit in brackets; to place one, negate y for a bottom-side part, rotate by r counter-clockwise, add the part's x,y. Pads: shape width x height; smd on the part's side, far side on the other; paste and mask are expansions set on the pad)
12LGA [mm] "LGA, 12-Leads, Body 2x2mm, Pitch 0.5mm"
  rect 0.41x0.28 smd: 1(-0.815,0.75) 2(-0.815,0.25) 3(-0.815,-0.25) 4(-0.815,-0.75) 7(0.815,-0.75) 8(0.815,-0.25) 9(0.815,0.25) 10(0.815,0.75)
  rect 0.28x0.41 smd: 5(-0.25,-0.815) 6(0.25,-0.815) 11(0.25,0.815) 12(-0.25,0.815)
  body extent -1,-1 1,1, height 1.01
0201#1 [mm] "Data from Kemet datasheet CC101_COM dated 7/28/11"
  rect 0.46x0.42 smd mask+0.048: 1(-0.33,0) 2(0.33,0)
  body extent -0.31,-0.16 0.31,0.16, height 0.26
0201#2 [mm] "Data from Kemet datasheet CC101_COM dated 7/28/11"
  rrect25% 0.35x0.35 smd mask+0.025: 1(-0.33,0) 2(0.33,0)
  body extent -0.31,-0.16 0.31,0.16, height 0.26
0201#3 [mm] "Data from Kemet datasheet CC101_COM dated 7/28/11"
  rrect25% 0.35x0.35 smd mask+0.048: 1(-0.33,0) 2(0.33,0)
  body extent -0.31,-0.16 0.31,0.16, height 0.26
0201_033 [mm] "SMD, 2-Leads, Height 0.33mm"
  rrect25% 0.35x0.35 smd mask+0.048: 1(-0.33,0) 2(0.33,0)
  body extent -0.31,-0.16 0.31,0.16, height 0.33
0402 [mm] "0402 from SM-752 data"
  rect 0.8x0.6 smd: 1(-0.6,0) 2(0.6,0)
  body extent -0.55,-0.3 0.55,0.3, height 0.6
0402S [mil] "Based on C0402S footprint from PADS legacy"
  rect 15x24 smd: 1(-20,0) 2(20,0)
  body extent -22,-12 22,12, height 24
0603 [mm] "0603 from SM-752 data"
  rect 1x0.95 smd: 1(-0.8,0) 2(0.8,0)
  body extent -0.87,-0.47 0.87,0.47, height 1
0805_HV [mil] "0805 with 30mil clearance between pads"
  rect 50x63 smd: 1(-40,0) 2(40,0)
  body extent -43,-29 43,29, height 57
AssemblyNote [mil] "Assembly Note"
AssemblyNoteLabel [mil] "Assembly Note for PCB Labels"
BoosterPack_40pin_J1J3 [mm] "Receptacle, 2.54mm, 10x2, TH"
  rrect6% 1.55x1.55 hole 1.02: 1(1.27,11.43)
  round 1.55 hole 1.02: 2(1.27,8.89) 3(1.27,6.35) 4(1.27,3.81) 5(1.27,1.27) 6(1.27,-1.27) 7(1.27,-3.81) 8(1.27,-6.35) 9(1.27,-8.89) 10(1.27,-11.43) 21(-1.27,11.43) 22(-1.27,8.89) 23(-1.27,6.35) 24(-1.27,3.81) 25(-1.27,1.27) 26(-1.27,-1.27) 27(-1.27,-3.81) 28(-1.27,-6.35) 29(-1.27,-8.89) 30(-1.27,-11.43)
  silkscreen extent -7.62,-12.95 7.62,12.95, body extent -2.48,-12.95 2.48,12.95, height 8.51
BoosterPack_40pin_J2J4 [mm] "Receptacle, 2.54mm, 10x2, TH"
  round 1.55 hole 1.02: 11(-1.27,-11.43) 12(-1.27,-8.89) 13(-1.27,-6.35) 14(-1.27,-3.81) 15(-1.27,-1.27) 16(-1.27,1.27) 17(-1.27,3.81) 18(-1.27,6.35) 19(-1.27,8.89) 20(-1.27,11.43) 31(1.27,-11.43) 32(1.27,-8.89) 33(1.27,-6.35) 34(1.27,-3.81) 35(1.27,-1.27) 36(1.27,1.27) 37(1.27,3.81) 38(1.27,6.35) 39(1.27,8.89) 40(1.27,11.43)
  silkscreen extent -7.62,-12.95 2.48,12.95, body extent -2.48,-12.95 2.48,12.95, height 8.51
CE_Mark_5mm [mil] "Minimum text height for CE Mark"
  silkscreen extent -138,-98 138,98
CONN_UFL-R-SMT-1 [mm] "Hirose recommended land pattern http://www.hirose.co.jp/cataloge_hp/e32119372.pdf 2009.2"
  rect 1.05x1 smd paste-0.1 mask-0.1: 1(-1.525,0)
  rect 2.2x1.05 smd paste-2 mask-2: 2(0,1.475) 3(0,-1.475)
  rect 2x0.9 on Top Solder: 2(0,1.5) 3(0,-1.5)
  rect 2x0.9 on Top Paste: 2(0,1.5) 3(0,-1.5)
  Top Layer keep-out region: -0.8,-0.7 1.1,-0.7 1.1,0.7 -0.8,0.7
  silkscreen extent -1.7,-1.7 1.7,1.7, body extent -1.55,-1.5 1.55,1.5, height 1.27
DRG0008B [mm] "SON, 8-Leads, Body 3x3mm, Pitch 0.5mm, Thermal Pad 2.4x1.45mm"
  oval 0.7x0.25 smd: 1(-1.35,0.75) 2(-1.35,0.25) 3(-1.35,-0.25) 4(-1.35,-0.75) 5(1.35,-0.75) 6(1.35,-0.25) 7(1.35,0.25) 8(1.35,0.75)
  rect 1.45x2.4 smd paste-0.75: 9(0,0)
  body extent -1.55,-1.55 1.55,1.55, height 0.81
DRL0006A-MFG [mm]
  rrect33% 0.67x0.3 smd paste+0 mask+0: 1(-0.74,0.5) 2(-0.74,0) 3(-0.74,-0.5) 4(0.74,-0.5) 5(0.74,0) 6(0.74,0.5)
  body extent -1.17,-1.1 1.17,1.1, height 0.25
EAST1616_RGB [mm] "SMD, 6-Leads, Body 1.6x1.6mm"
  rect 0.4x0.55 smd: 1(-0.725,0.675) 2(-0.725,-0.675) 5(0.725,0.675) 6(0.725,-0.675)
  rect 0.5x0.7 smd: 3(0,0.75) 4(0,-0.75)
  silkscreen extent -0.9,-1.2 0.9,0.1, body extent -0.8,-0.8 0.8,0.8, height 0.5
ESD_Overlay_Medium [mil]
  silkscreen extent -127,-109 125,110
Ethertronics_M830520 [mm] "SMD, 6-Leads, Body 8x3mm"
  rect 0.9x1.1 smd mask+0: 1(-1,3.4) 2(-1,0) 3(-1,-3.4) 4(1,-3.4) 5(1,0) 6(1,3.4)
  silkscreen extent -1.8,-2.4 1.5,2.4, body extent -1.5,-4 1.5,4, height 1.33
FCC_disclaimer [mil]
Fiducial10-20 [mm]
  round 1 smd mask+0.5: 1(0,0)
  Top Layer keep-out circle w1.178: c0,0 r0.5
FP-APS1604M-SQRX-SN_SOP8-IPC_C [mil]
  rrect18% 67.18x21.34 smd paste+0 mask+0: 1(-91.82,75)
  rrect100% 67.18x21.34 smd paste+0 mask+0: 2(-91.82,25) 3(-91.82,-25) 4(-91.82,-75) 5(91.82,-75) 6(91.82,-25) 7(91.82,25) 8(91.82,75)
  silkscreen extent -39,-96 39,96, body extent -129,-100 129,100, height 10
FP-BLM18-0_15-t0_8-MFG [mm]
  rect 0.65x0.7 smd paste+0 mask+0: 1(-0.675,0) 2(0.675,0)
  body extent -1.1,-0.58 1.1,0.58, height 0.25
FP-CAT24C08TDI-GT3_TSOT-23-5-IPC_C [mm]
  rrect21% 0.94x0.486 smd paste+0 mask+0: 1(-1.115,0.95)
  rrect100% 0.94x0.486 smd paste+0 mask+0: 2(-1.115,0) 3(-1.115,-0.95) 4(1.116,-0.95) 5(1.116,0.95)
  body extent -1.69,-1.55 1.69,1.55, height 0.25
FP-CTL0603FRD1T_0603-MFG [mm]
  rrect13% 0.8x0.8 smd paste+0 mask+0: 1(-0.75,0) 2(0.75,0)
  body extent -1.25,-0.55 1.25,0.55, height 0.25
FP-DEA162450BT-1295A1_SMT_FILTER_1MM60_0MM80-MFG [mm]
  rrect33% 0.5x0.3 smd paste+0 mask+0: 1(-0.85,0) 3(0.85,0)
  rrect20% 0.8x0.5 smd paste+0 mask+0: 2(0,-0.45) 4(0,0.45)
  body extent -1.2,-0.8 1.2,0.8, height 0.25
FP-DPX167125DT-8197B1_SMD6-MFG [mm]
  rrect33% 0.3x0.6 smd paste+0 mask+0: 1(-0.55,-0.45) 2(0,-0.45) 3(0.55,-0.45) 4(0.55,0.45) 5(0,0.45) 6(-0.55,0.45)
  body extent -0.95,-0.85 0.95,0.85, height 0.25
FP-ERJ-1GNF49R9C_0201-MFG [mm]
  rrect40% 0.25x0.3 smd paste+0 mask+0: 1(-0.3,0) 2(0.3,0)
  body extent -0.53,-0.27 0.53,0.27, height 0.25
FP-ERJ-2GEJ514X_0402-MFG [mm]
  rrect21% 0.475x0.5 smd paste+0 mask+0: 1(-0.512,0) 2(0.513,0)
  body extent -0.5,-0.25 0.5,0.25, height 0.4
FP-GRM033D70J105ME01D_0201-MFG [mm]
  rrect33% 0.3x0.35 smd paste+0 mask+0: 1(-0.283,0) 2(0.282,0)
  body extent -0.53,-0.3 0.53,0.3, height 0.25
FP-GRM188Z71A106MA73J_0603-MFG [mm]
  rrect13% 0.75x0.9 smd paste+0 mask+0: 1(-0.775,0) 2(0.775,0)
  body extent -1.25,-0.6 1.25,0.6, height 0.25
FP-GRM0335C1E331FA01D_0201-MFG [mm]
  rrect40% 0.25x0.3 smd paste+0 mask+0: 1(-0.238,0) 2(0.238,0)
  body extent -0.46,-0.27 0.46,0.27, height 0.25
FP-GRM0335C1H1R0CA01D_0201-MFG [mm]
  rrect25% 0.35x0.35 smd mask+0.013: 1(-0.33,0) 2(0.33,0)
  body extent -0.46,-0.27 0.46,0.27, height 0.25
FP-GRM0335C1H2R4BA01D_0201-MFG [mm]
  rrect25% 0.35x0.35 smd mask+0.013: 1(-0.33,0) 2(0.33,0)
  body extent -0.46,-0.27 0.46,0.26, height 0.25
FP-GRM0335C1H6R2BA01D_0201-MFG [mm]
  rrect40% 0.25x0.3 smd paste+0 mask+0: 1(-0.238,0) 2(0.238,0)
  body extent -0.46,-0.27 0.46,0.27, height 0.25
FP-IS25WJ032F-JNLE_SOIC8-IPC_C [mil]
  rrect18% 73.78x21.34 smd paste+0 mask+0: 1(-91.18,75)
  rrect100% 73.78x21.34 smd paste+0 mask+0: 2(-91.18,25) 3(-91.18,-25) 4(-91.18,-75) 5(91.18,-75) 6(91.18,-25) 7(91.18,25) 8(91.18,75)
  body extent -132,-100 132,100, height 10
FP-LQP03HQ3N9B02D_0201-MFG [mm]
  rrect25% 0.35x0.35 smd paste+0 mask+0: 1(-0.3,0) 2(0.3,0)
  body extent -0.55,-0.27 0.55,0.26, height 0.25
FP-PCB.SMAFSTJ.B.HT_SMT_SMA_JACK-MFG [mm]
  round 1.55 smd paste+0 mask+0: 1(0,0)
  rrect6% 1.8x1.8 smd paste+0 mask+0: 2(-2.75,2.75) 3(2.75,2.75) 4(-2.75,-2.75) 5(2.75,-2.75)
  silkscreen extent -3.6,-3.6 3.6,3.6, body extent -3.75,-3.75 3.75,3.75, height 0.25
FP-TZ3359DAAO73_SMT2_1MM65_1MM05-MFG [mm]
  rrect20% 0.5x1 smd paste+0 mask+0: 1(-0.55,0) 2(0.55,0)
  body extent -0.97,-0.67 0.97,0.67, height 0.25
FP-TZ3877AAAO44_SMT4_2MM05_1MM65-MFG [mm]
  rrect12% 0.95x0.85 smd paste+0 mask+0: 1(-0.725,-0.575) 2(0.725,-0.575) 3(0.725,0.575) 4(-0.725,0.575)
  body extent -1.3,-1.1 1.3,1.1, height 0.25
FP-USB4125-GF-A-0190_CONN_USB-MFG [mm]
  rrect100% 1.1x1.7 hole 1.2 slot 0.6 at 0 deg paste-1000 mask+0: 1(-4.32,3) 2(4.32,3) 3(-4.32,-0.8) 4(4.32,-0.8)
  rrect14% 0.7x1.2 smd paste+0 mask+0: A5(-0.5,3) B5(0.5,3)
  rrect13% 0.76x1.2 smd paste+0 mask+0: A9(1.52,3) B9(-1.52,3)
  rrect13% 0.8x1.2 smd paste+0 mask+0: A12(2.75,3) B12(-2.75,3)
  silkscreen extent -4.59,0.43 4.59,1.78, body extent -4.47,-3.4 4.47,3.4, height 3.51
Label_650x200 [mil] "Thermal Transfer Label"
  round 1 on Mech13: 0(0,0)
  silkscreen extent -325,-100 325,100, body extent -325,-100 325,100, height 1
LaunchPadRocket_Small [mil]
  silkscreen extent -241,-202 182,153
Molex_693071010811 [mm] "MicroSD Card Connector, R/A, SMT"
  rrect12% 0.8x1.5 smd: 1(-1.942,3.1) 2(-0.842,2.7) 3(0.258,3.1) 4(1.358,3.3) 5(2.458,3.1) 6(3.558,3.3) 7(4.658,3.1) 8(5.758,3.1)
  rrect7% 1.4x1.9 smd: 9(-6.602,6.95) 9(6.548,5.95)
  rrect7% 1.8x1.4 smd: 10(-0.752,-7.2) 10(4.948,-7.2)
  silkscreen extent -6.99,-7.6 7.01,7.6, body extent -7,-7.6 7,7.6, height 1.83
RSH0056D-MFG [mm]
  rrect100% 0.7x0.2 smd paste+0 mask+0: 1(-3.35,2.6) 2(-3.35,2.2) 3(-3.35,1.8) 4(-3.35,1.4) 5(-3.35,1) 6(-3.35,0.6) 7(-3.35,0.2) 8(-3.35,-0.2) 9(-3.35,-0.6) 10(-3.35,-1) 11(-3.35,-1.4) 12(-3.35,-1.8) 13(-3.35,-2.2) 14(-3.35,-2.6) 29(3.35,-2.6) 30(3.35,-2.2) 31(3.35,-1.8) 32(3.35,-1.4) 33(3.35,-1) 34(3.35,-0.6) 35(3.35,-0.2) 36(3.35,0.2) 37(3.35,0.6) 38(3.35,1) 39(3.35,1.4) 40(3.35,1.8) 41(3.35,2.2) 42(3.35,2.6)
  rrect100% 0.2x0.7 smd paste+0 mask+0: 15(-2.6,-3.35) 16(-2.2,-3.35) 17(-1.8,-3.35) 18(-1.4,-3.35) 19(-1,-3.35) 20(-0.6,-3.35) 21(-0.2,-3.35) 22(0.2,-3.35) 23(0.6,-3.35) 24(1,-3.35) 25(1.4,-3.35) 26(1.8,-3.35) 27(2.2,-3.35) 28(2.6,-3.35) 43(2.6,3.35) 44(2.2,3.35) 45(1.8,3.35) 46(1.4,3.35) 47(1,3.35) 48(0.6,3.35) 49(0.2,3.35) 50(-0.2,3.35) 51(-0.6,3.35) 52(-1,3.35) 53(-1.4,3.35) 54(-1.8,3.35) 55(-2.2,3.35) 56(-2.6,3.35)
  rrect2% 5.3x5.3 smd paste-1000 mask+0: 57(0,0)
  silkscreen extent -3.57,-3.57 3.57,3.57, body extent -3.8,-3.8 3.8,3.8, height 0.25
RTJ0020D [mm] "WQFN-20"
  rrect42% 0.6x0.24 smd: 1(-1.9,1) 2(-1.9,0.5) 3(-1.9,0) 4(-1.9,-0.5) 5(-1.9,-1) 11(1.9,-1) 12(1.9,-0.5) 13(1.9,0) 14(1.9,0.5) 15(1.9,1)
  rrect42% 0.24x0.6 smd: 6(-1,-1.9) 7(-0.5,-1.9) 8(0,-1.9) 9(0.5,-1.9) 10(1,-1.9) 16(1,1.9) 17(0.5,1.9) 18(0,1.9) 19(-0.5,1.9) 20(-1,1.9)
  rrect4% 2.7x2.7 smd paste-1.4: 21(0,0)
  rrect8% 1.19x1.19 on Top Paste: 21A(-0.695,0.695) 21B(0.695,0.695) 21C(-0.695,-0.695) 21D(0.695,-0.695)
  body extent -2,-2 2,2, height 0.81
Samtec_FTSH-105-01-x-D-K [mm] "Header, 1.27 mm, 5x2, TH"
  rect 1.05x1.05 hole 0.71: 1(-0.635,2.54)
  round 1.05 hole 0.71: 2(0.635,2.54) 3(-0.635,1.27) 4(0.635,1.27) 5(-0.635,0) 6(0.635,0) 7(-0.635,-1.27) 8(0.635,-1.27) 9(-0.635,-2.54) 10(0.635,-2.54)
  silkscreen extent -2.54,-3.17 2.54,3.2, body extent -2.54,-3.17 2.54,3.1, height 5.73
SNT-100-BK-G [mil] "Samtec STEP model"
  round 1 on Mech3: 0(0,0)
  body extent -100,-50 100,50, height 344
SOD-123 [mm] "On Semi recommended land pattern"
  rect 0.915x1.22 smd: 1(-1.637,0) 2(1.637,0)
  body extent -1.93,-0.9 1.93,0.9, height 1.35
SOD-523F_Bi [mm] "NXP Semiconductor recommended land pattern, nominal STEP model"
  rrect17% 0.8x0.6 smd paste-0.05: 1(-0.55,0) 2(0.55,0)
  body extent -0.8,-0.4 0.8,0.4, height 0.72
SOT-23 [mm] "SOT23, 3-Leads, Body 2.9x1.3mm, Pitch 0.95mm, Lead Span 2.5mm, IPC Medium Density"
  rrect50% 1x0.6 smd: 1(-1.2,0.95) 2(-1.2,-0.95) 3(1.2,0)
  body extent -1.16,-1.45 1.21,1.45, height 1
Sullins_SFH11-xxxC-D10-RA [mm] "Receptacle, 2.54mm, 10x2, R/A, TH"
  rrect50% 1.53x1.53 hole 1.02: 1(-11.43,1.27)
  round 1.53 hole 1.02: 2(-11.43,-1.27) 3(-8.89,1.27) 4(-8.89,-1.27) 5(-6.35,1.27) 6(-6.35,-1.27) 7(-3.81,1.27) 8(-3.81,-1.27) 9(-1.27,1.27) 10(-1.27,-1.27) 11(1.27,1.27) 12(1.27,-1.27) 13(3.81,1.27) 14(3.81,-1.27) 15(6.35,1.27) 16(6.35,-1.27) 17(8.89,1.27) 18(8.89,-1.27) 19(11.43,1.27) 20(11.43,-1.27)
  body extent -15.24,-11.37 15.24,1.47, height 7
SW_1188E [mm] "SMD, 4-Leads, Body 7.8x3.5mm"
  rrect10% 1x1.45 smd: 1(-1.1,3.375) 2(-1.1,-3.375)
  rrect11% 1.3x0.9 smd: 3(0.7,2.1) 4(0.7,-2.1)
  round 0 hole 0.9 unplated: ""(-0.35,1.15) ""(-0.35,-1.15)
  body extent -2.55,-3.9 1.05,3.9, height 3.5
TI_Horizontal_Overlay_Medium [mil]
  silkscreen extent -751,-94 -558,94
TI_Stacked_Overlay_Small [mil]
  silkscreen extent -418,-98 418,98
WEEE_Minimum [mil] "WEEElie bin"
  silkscreen extent -95,-172 99,104
WL-SMCW_GREEN [mm] "WURTH"
  rect 0.8x0.8 smd: 1(-0.8,0) 2(0.8,0)
  body extent -0.85,-0.45 0.85,0.45, height 0.8
WL-SMCW_YELLOW [mm] "WURTH"
  rect 0.8x0.8 smd: 1(-0.8,0) 2(0.8,0)
  body extent -0.85,-0.45 0.85,0.45, height 0.8
WURTH_61300211121 [mm] "Header, 2.54mm, 2x1, TH"
  rect 1.65x1.65 hole 1.15: 1(-1.27,0)
  round 1.65 hole 1.15: 2(1.27,0)
  silkscreen extent -2.54,-1.27 2.54,1.6, body extent -2.54,-1.27 2.54,1.27, height 8.54
WURTH_61300311121 [mm] "Header, 2.54mm, 3x1, TH"
  rect 1.65x1.65 hole 1.15: 1(-2.54,0)
  round 1.65 hole 1.15: 2(0,0) 3(2.54,0)
  silkscreen extent -3.81,-1.27 3.81,1.6, body extent -3.81,-1.27 3.81,1.27, height 8.54

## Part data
C1 C13 C14 C17 C18: library part CMP-0064969-1, "CAP, CERM, 0.1 uF, 10 V,+/- 10%, X7S, 0201", Cap_Case=0201, Manufacturer=MuRata, Supplier Part Number 1=490-14450-1-ND, TempCo=X7S, Tolerance_%=10%, Value1=Unknown, Value2=10V, ValueDisplayed=0.1uF
C2 C3 C4 C5: library part CMP-0092206-1, "Chip Multilayer Ceramic Capacitors for General Purpose, 0603, 10uF, X7R, 15%, 20%, 10V", Manufacturer=Murata, Operating Temperature Range="-55°C to +125°C", TempCo=15%, Temperature Characteristic=X7R, Tolerance_%=20%, ValueDisplayed=10uF
C6 C7: library part CMP-0080076-1, "CAP, CERM, 4.7 pF, 50 V,+/- 3%, C0G/NP0, 0201", Cap_Case=0201, Manufacturer=MuRata, Supplier Part Number 1=490-11332-1-ND, TempCo=C0G/NP0, Tolerance_%=3%, Value2=50V, ValueDisplayed=4.7pF
C8 C9 C10 C11 C30 C36: library part CMP-0091210-1, "Chip Multilayer Ceramic Capacitors for General Purpose, 0201, 2.4pF, C0G, 30ppm/°C, 0.1pF, 50V", Manufacturer=Murata, Operating Temperature Range="-55°C to +125°C", TempCo=30ppm/°C, Temperature Characteristic=C0G, ValueDisplayed=2.4pF
C12 C15 C31 C32: library part CMP-0098216-1, "Chip Multilayer Ceramic Capacitors for General Purpose, 0201, 330pF, C0G, 30ppm/°C, 1%, 25V", Manufacturer=Murata, Operating Temperature Range="-55°C to +125°C", TempCo=30ppm/°C, Temperature Characteristic=C0G, Tolerance_%=1%, ValueDisplayed=330pF
C16 C22 C24 C25 C33 C34 C35 C38 C40 C41 C42: library part CMP-0064969-1, "CAP, CERM, 0.1 uF, 10 V,+/- 10%, X7S, 0201", Cap_Case=0201, Manufacturer=MuRata, Supplier Part Number 1=490-14450-1-ND, TempCo=X7S, Value1=Unknown, Value2=10V, ValueDisplayed=0.1uF
C19: library part CMP-0078218-1, "CAP, CERM, 0.01 µF, 16 V,+/- 10%, X7R, 0402", Cap_Case=0402, Manufacturer=Kemet, Supplier Part Number 1=399-1038-1-ND, TempCo=X7R, Tolerance_%=10%, Value2=16V, ValueDisplayed=0.01µF
C20 C21: library part CMP-0096092-1, "Chip Multilayer Ceramic Capacitors for General Purpose, 0201, 6.2pF, C0G, 30ppm/°C, 0.1pF, 50V", Manufacturer=Murata, Operating Temperature Range="-55°C to +125°C", TempCo=30ppm/°C, Temperature Characteristic=C0G, Tolerance_%=1.6%, ValueDisplayed=6.2pF
C23 C27: library part CMP-0006624-2, "CAP, CERM, 1 uF, 6.3 V, +/- 20%, X7R, 0402", Cap_Case=0402, Manufacturer=MuRata, Supplier Part Number 1=490-9665-1-ND, TempCo=X7R, Tolerance_%=20%, Value1=Unknown, Value2=6.3V, ValueDisplayed=1uF
C26 C29: library part CMP-0095016-1, "Chip Multilayer Ceramic Capacitors for General Purpose, 0201, 1.0uF, X7T, +22%/-33%, 20%, 6.3V", Manufacturer=Murata, Operating Temperature Range="-55°C to +125°C", TempCo=+22%/-33%, Temperature Characteristic=X7T, Tolerance_%=20%, ValueDisplayed=1.0uF
C28: library part CMP-0090893-1, "Chip Multilayer Ceramic Capacitors for General Purpose, 0201, 1.0pF, C0G, 30ppm/°C, 0.25pF, 50V", Manufacturer=Murata, Operating Temperature Range="-55°C to +125°C", TempCo=30ppm/°C, Temperature Characteristic=C0G, ValueDisplayed=1.0pF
